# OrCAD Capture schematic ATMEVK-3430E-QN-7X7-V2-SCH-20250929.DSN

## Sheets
1 10. VDDIO-VCCIO Tracking: size B; title: ATM3430E EVALUATION BOARD; rev: 2; note: 084-23-511-xxxx
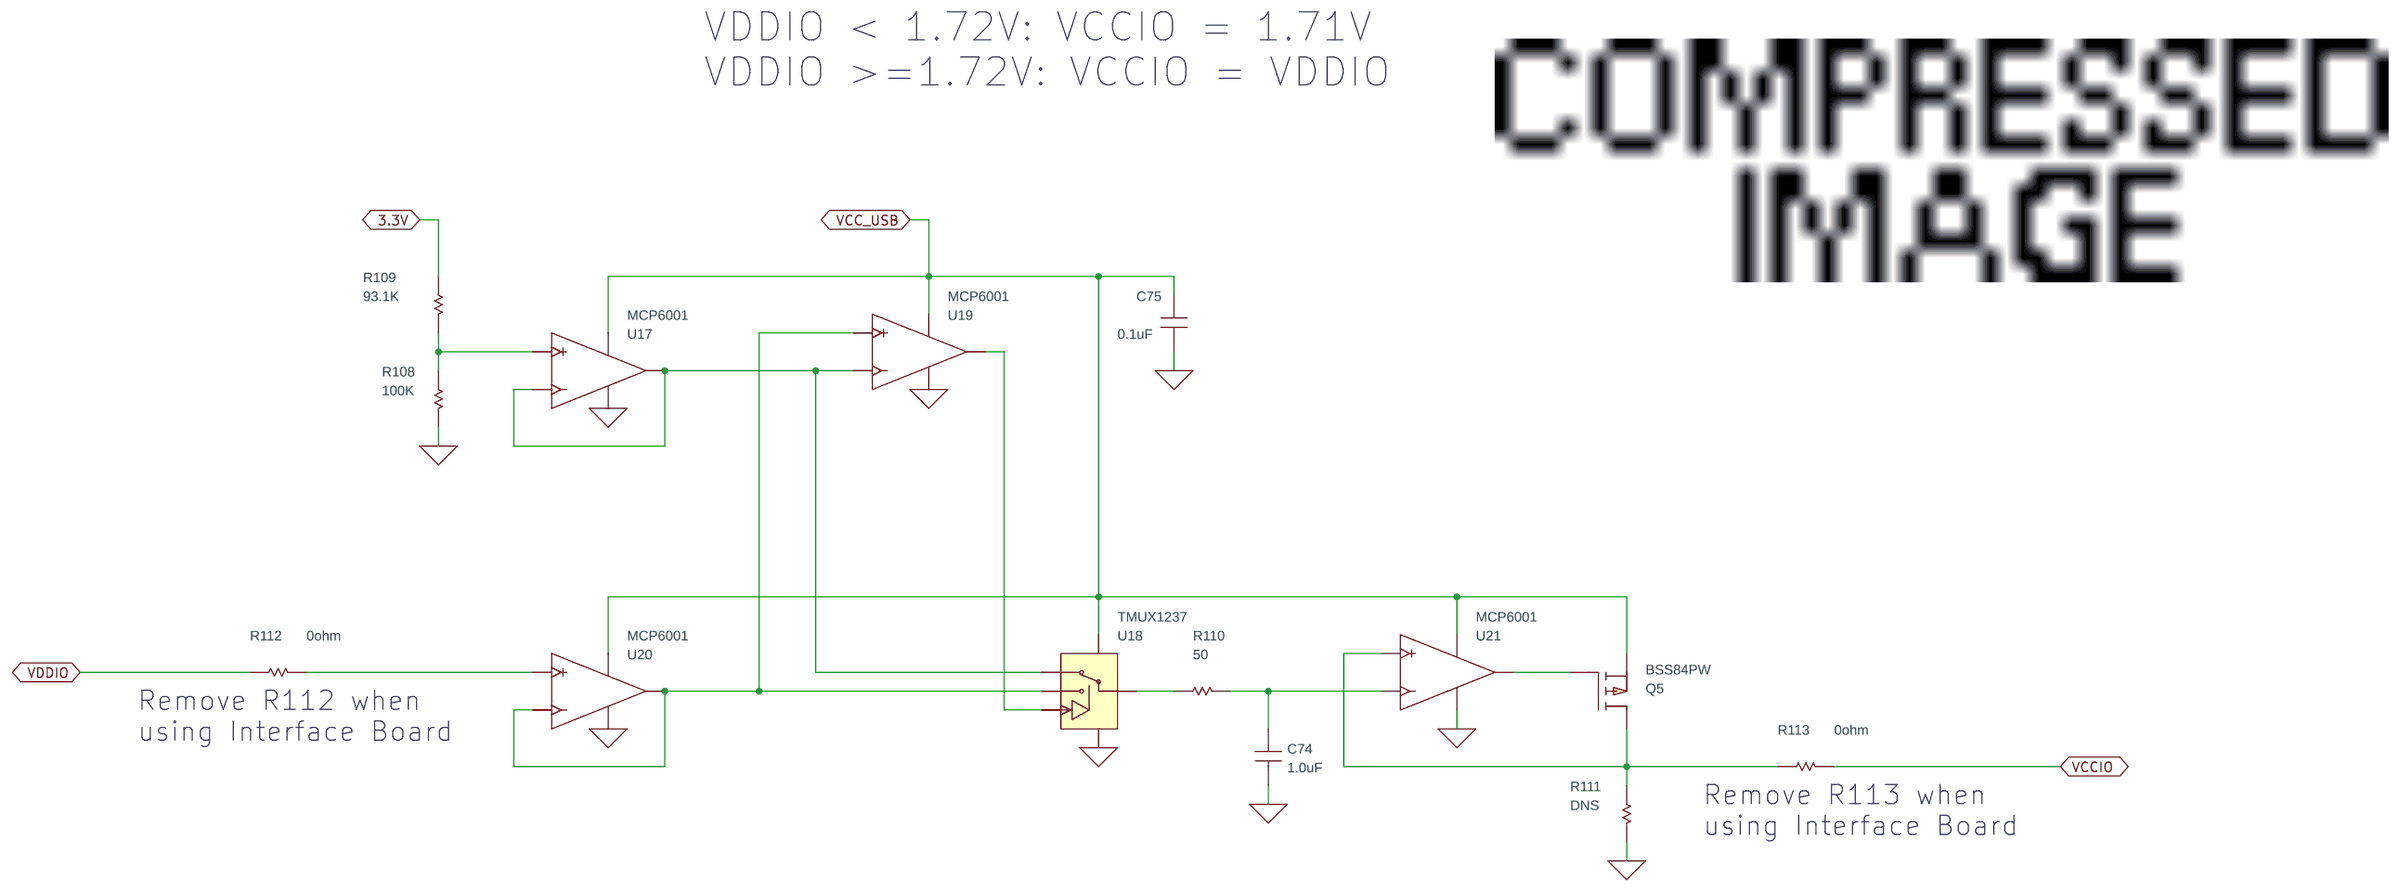
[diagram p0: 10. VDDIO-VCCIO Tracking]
2 11. Power Configuration
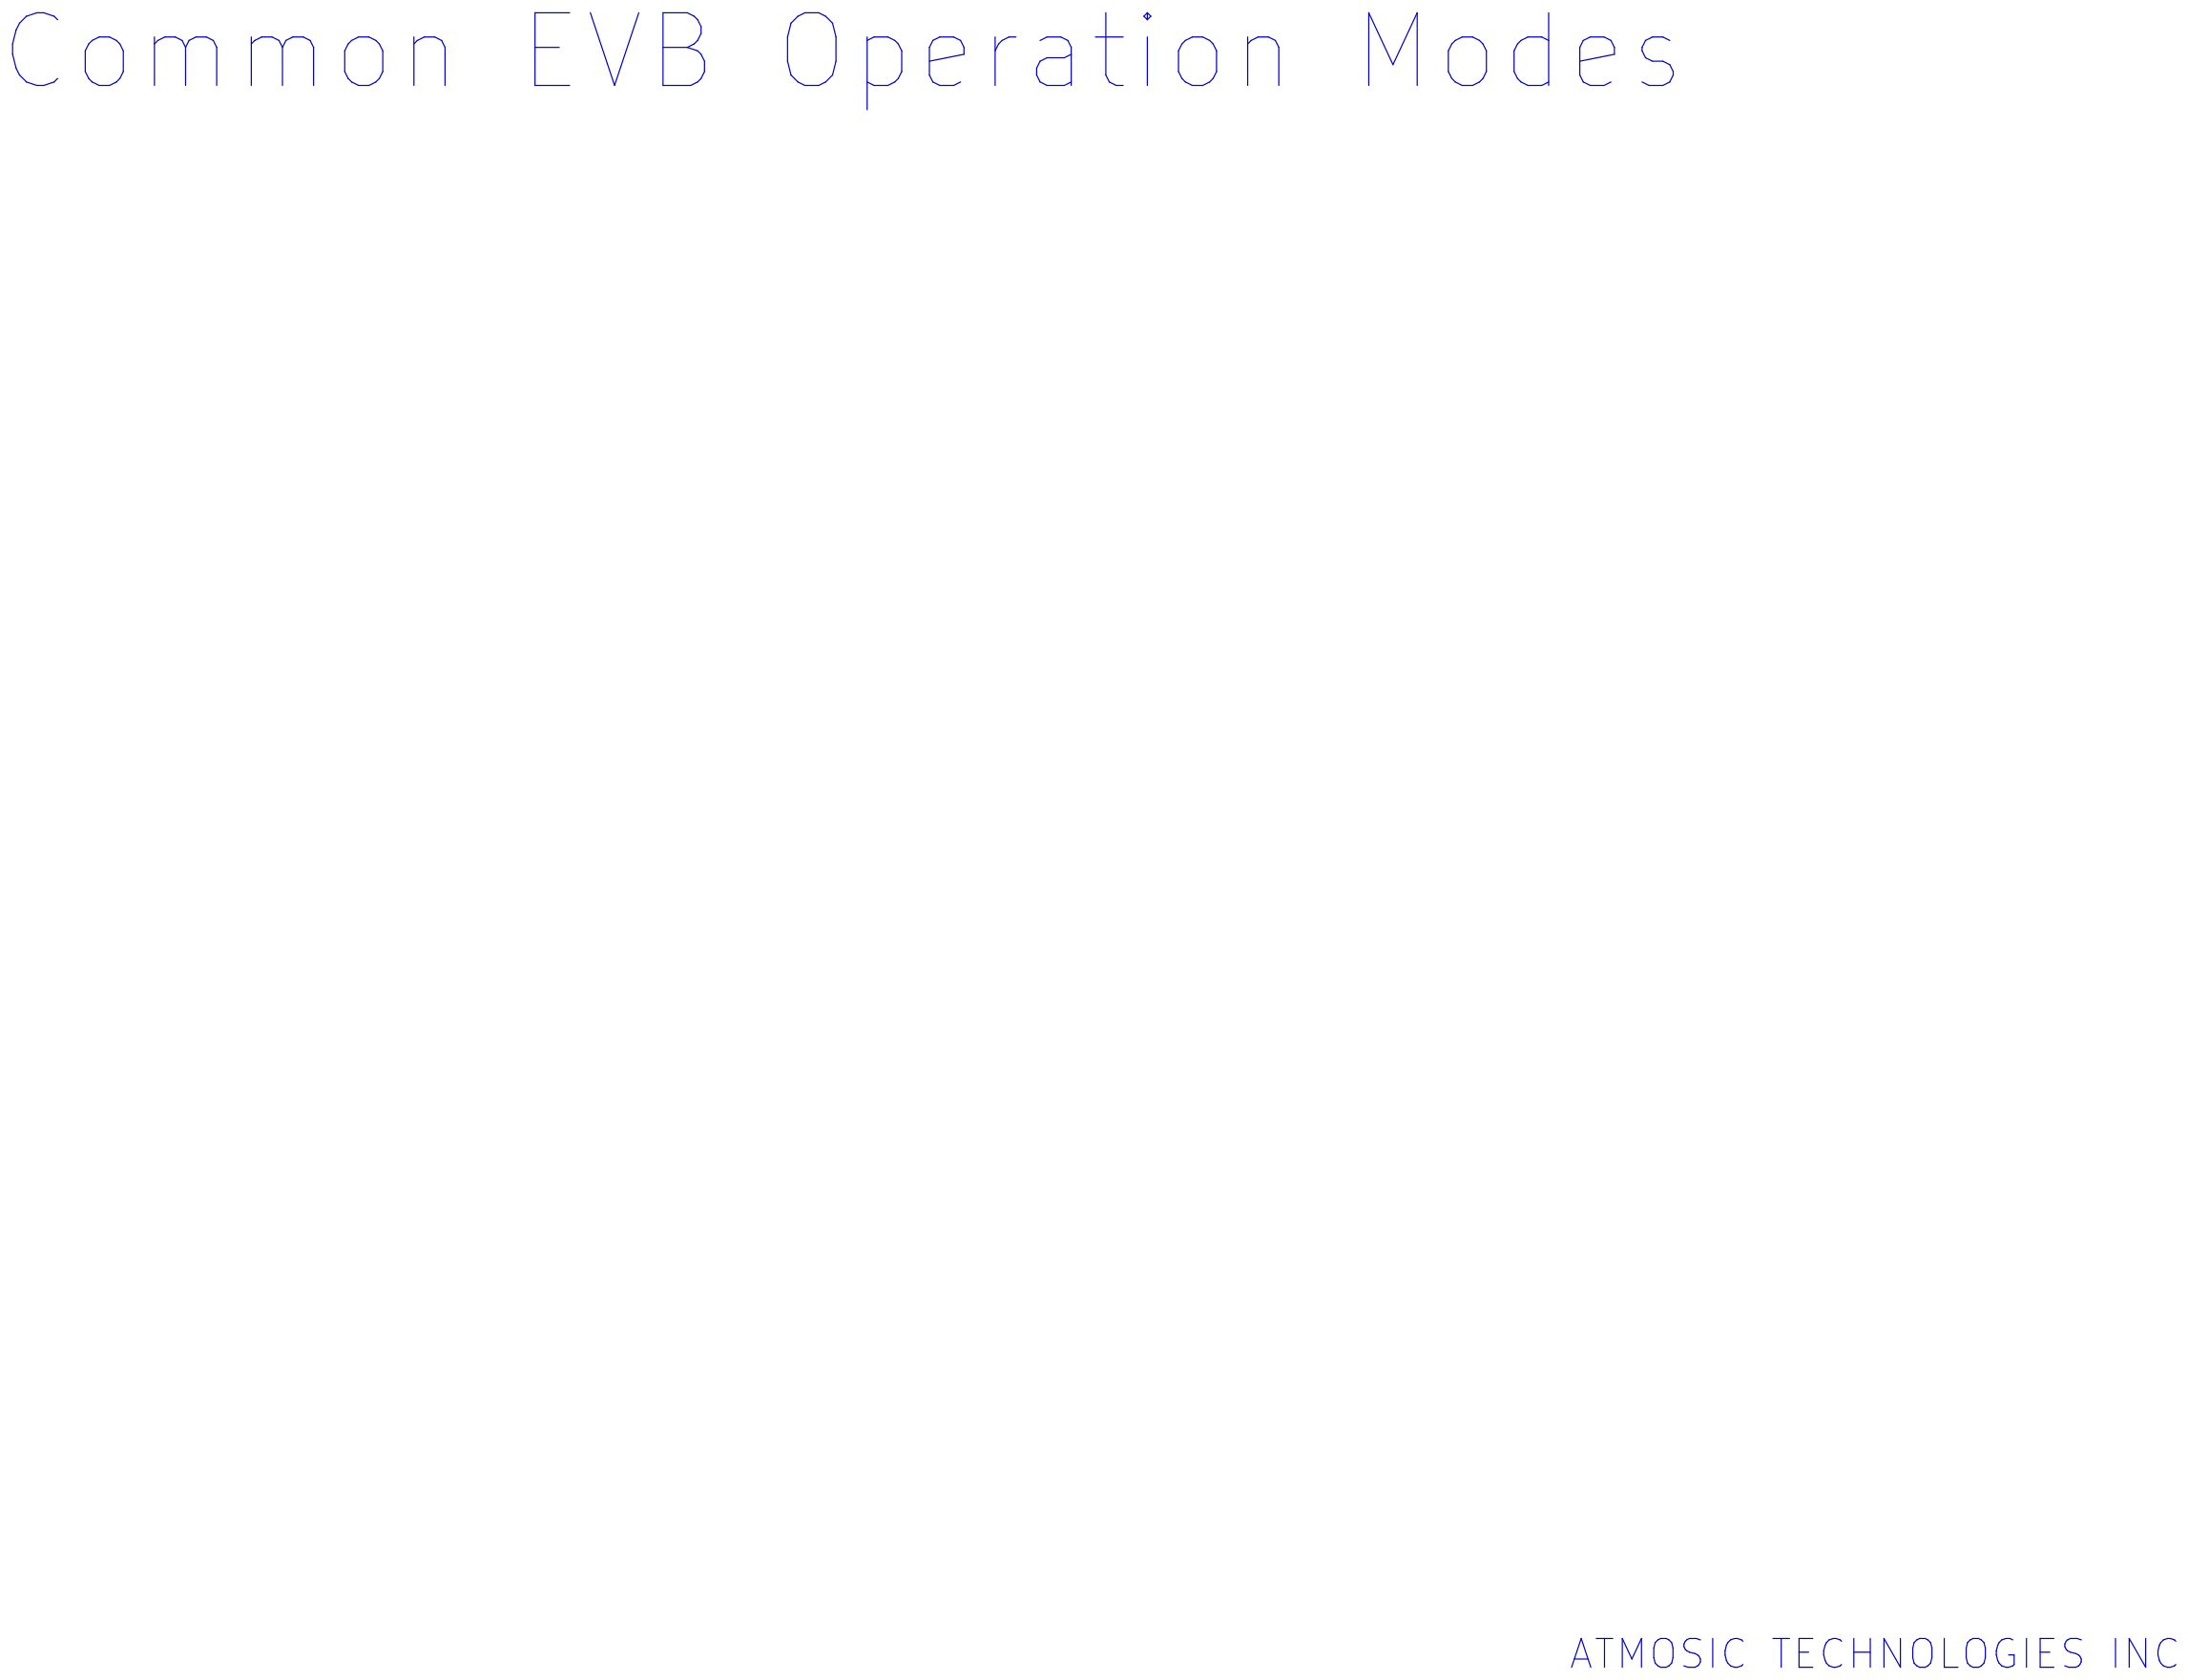
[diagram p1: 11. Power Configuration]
3 01. TITLE
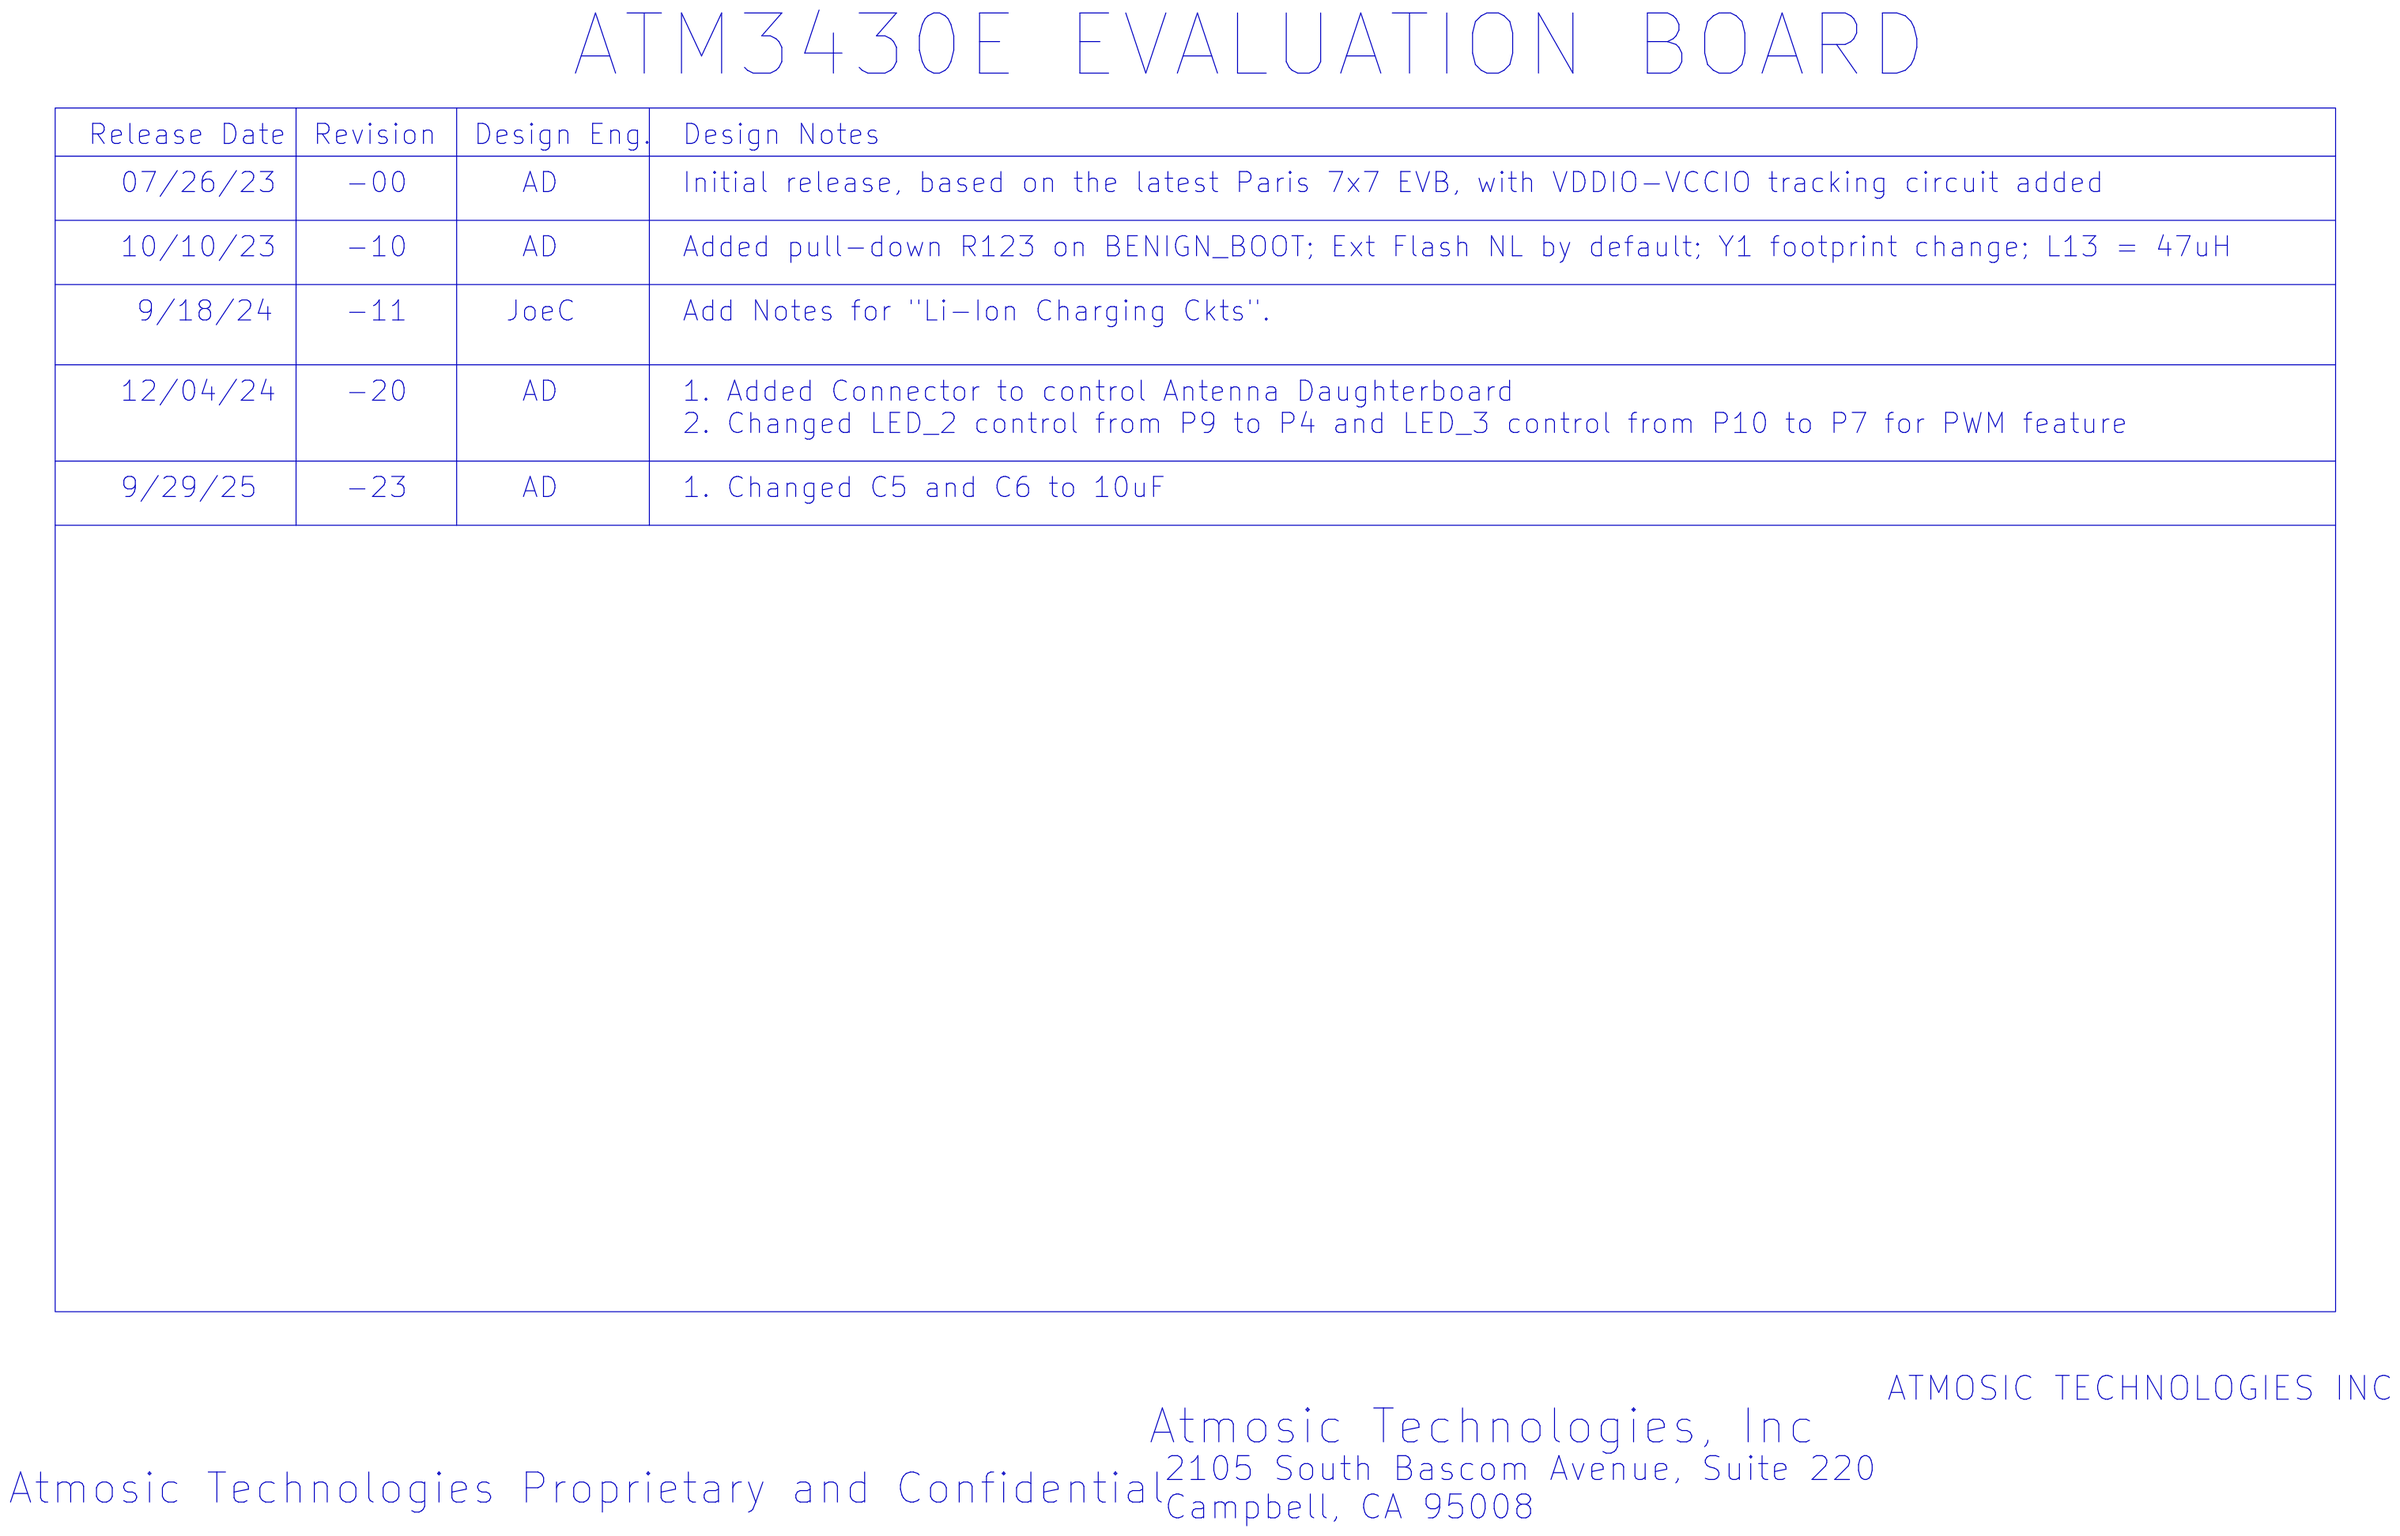
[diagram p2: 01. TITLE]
4 02. Block Diagram
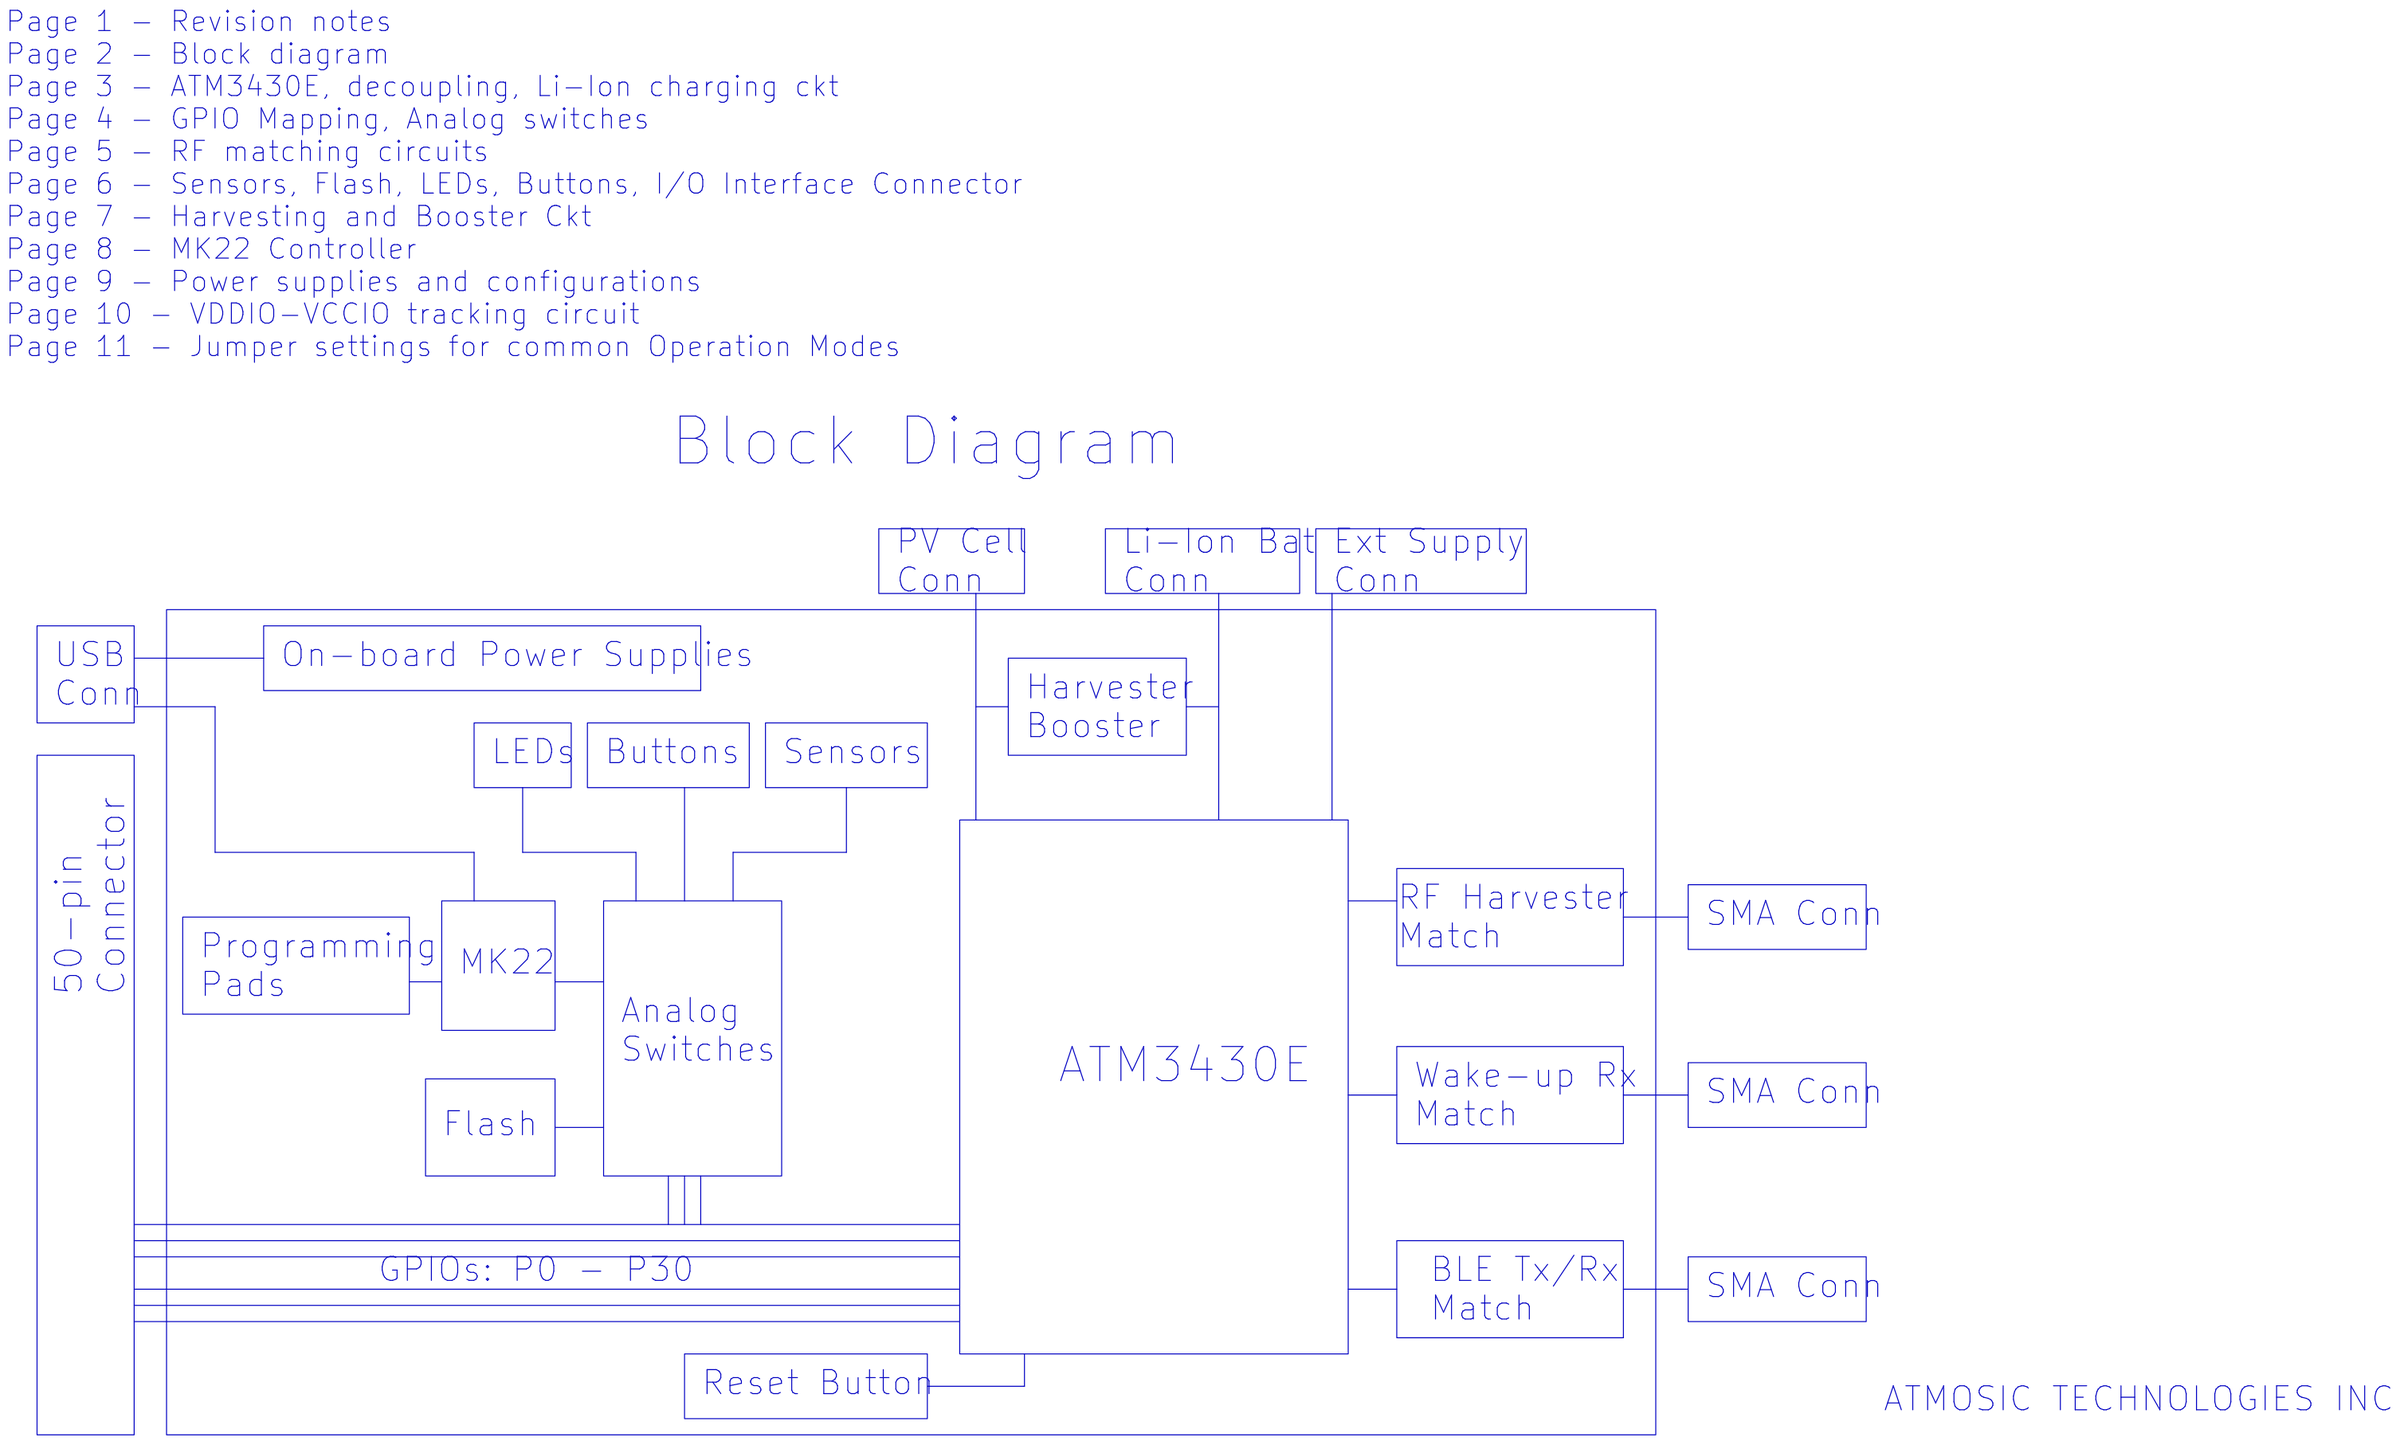
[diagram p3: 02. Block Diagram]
5 03. ATM3430E: size B
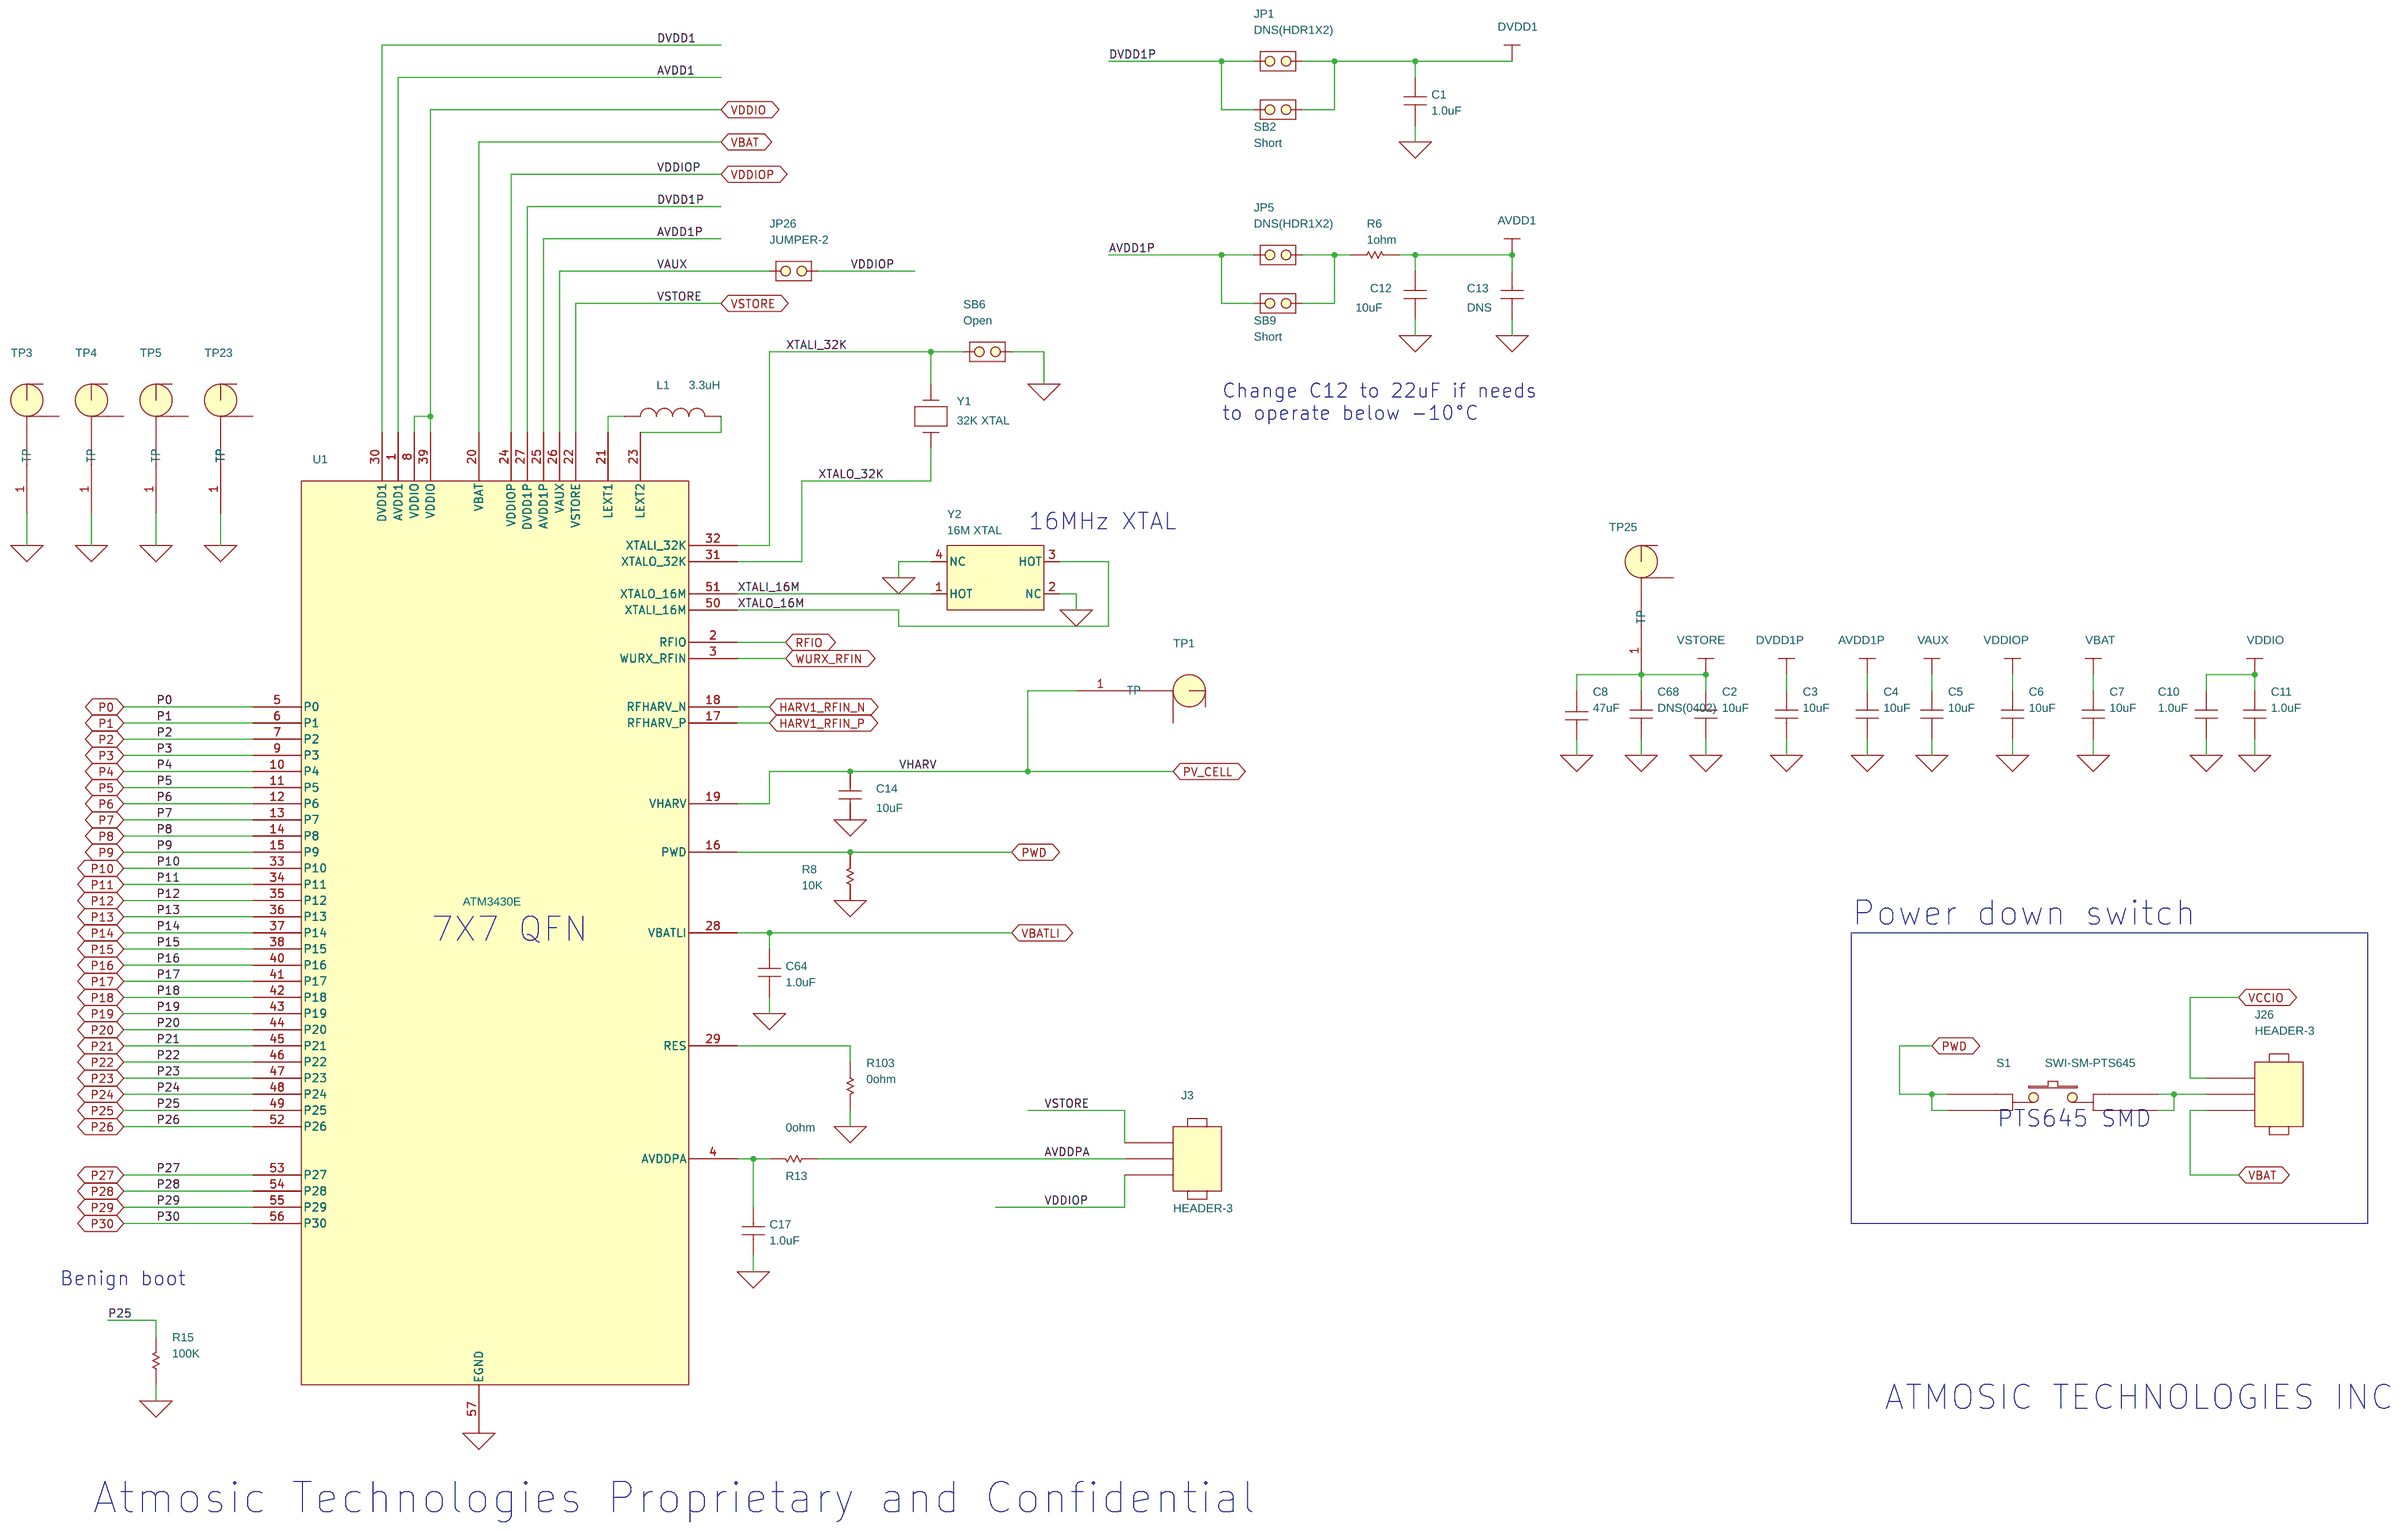
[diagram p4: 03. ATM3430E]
6 04. GPIO Mapping: size B
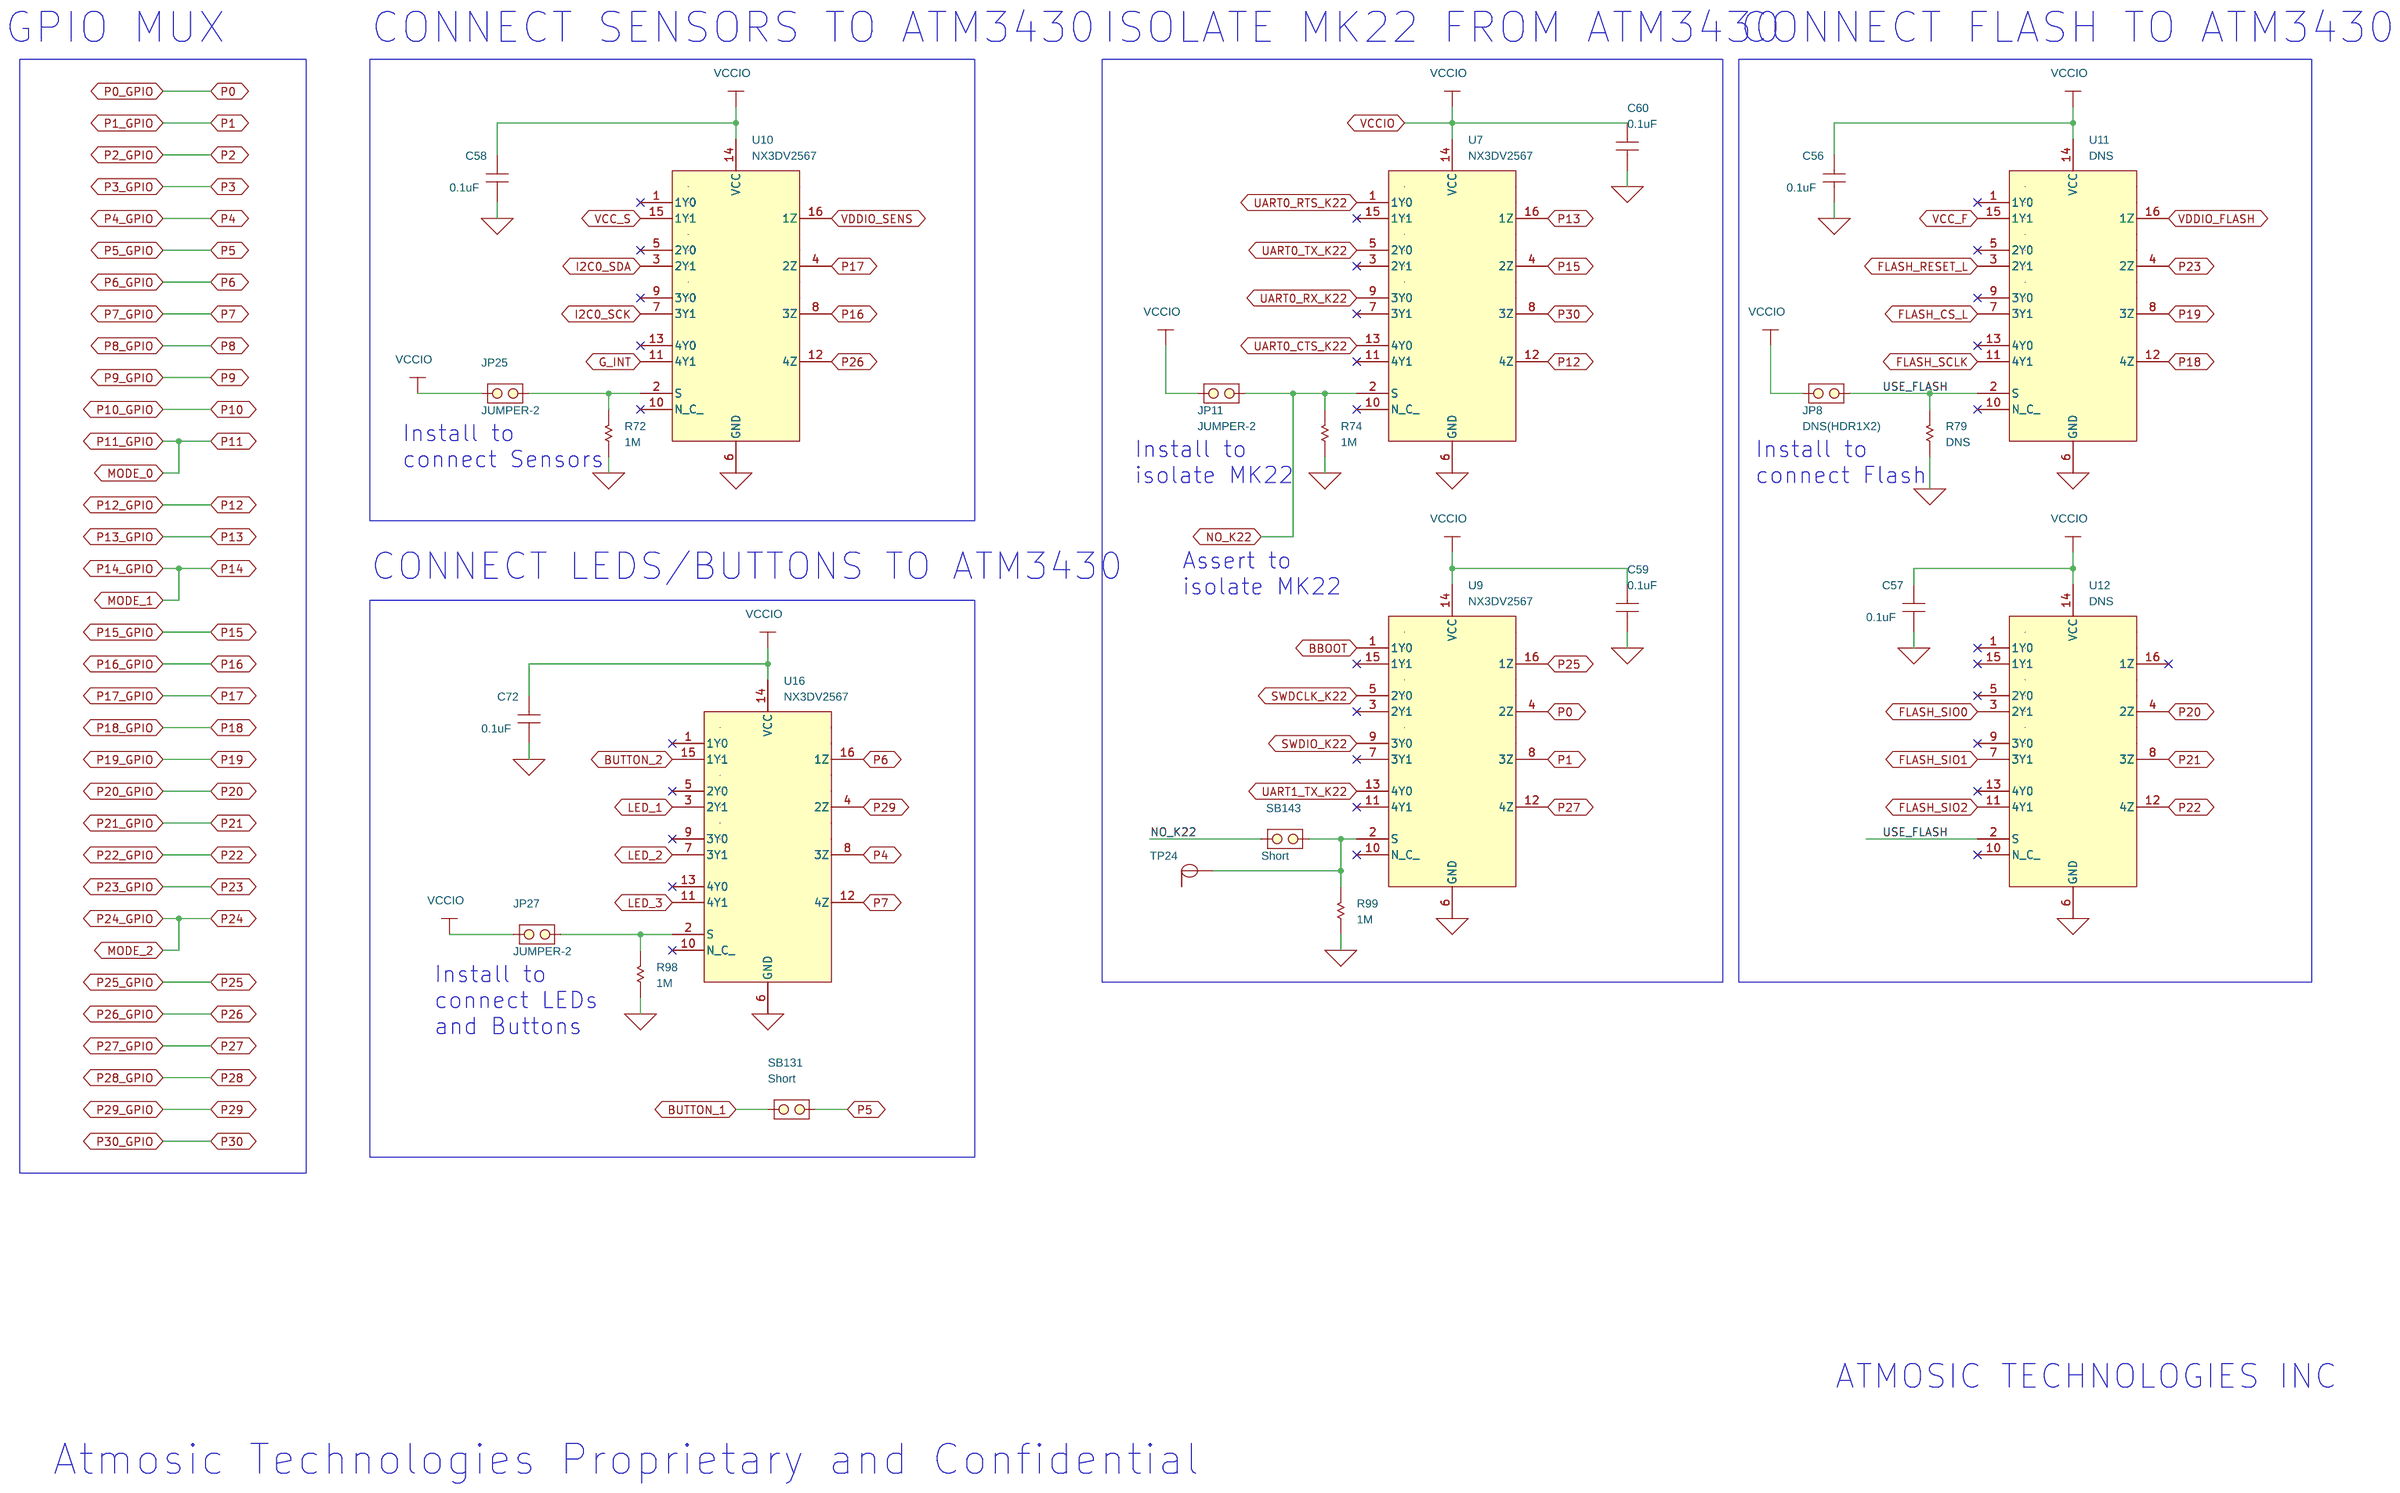
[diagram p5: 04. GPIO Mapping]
7 07. Harvesting: size B
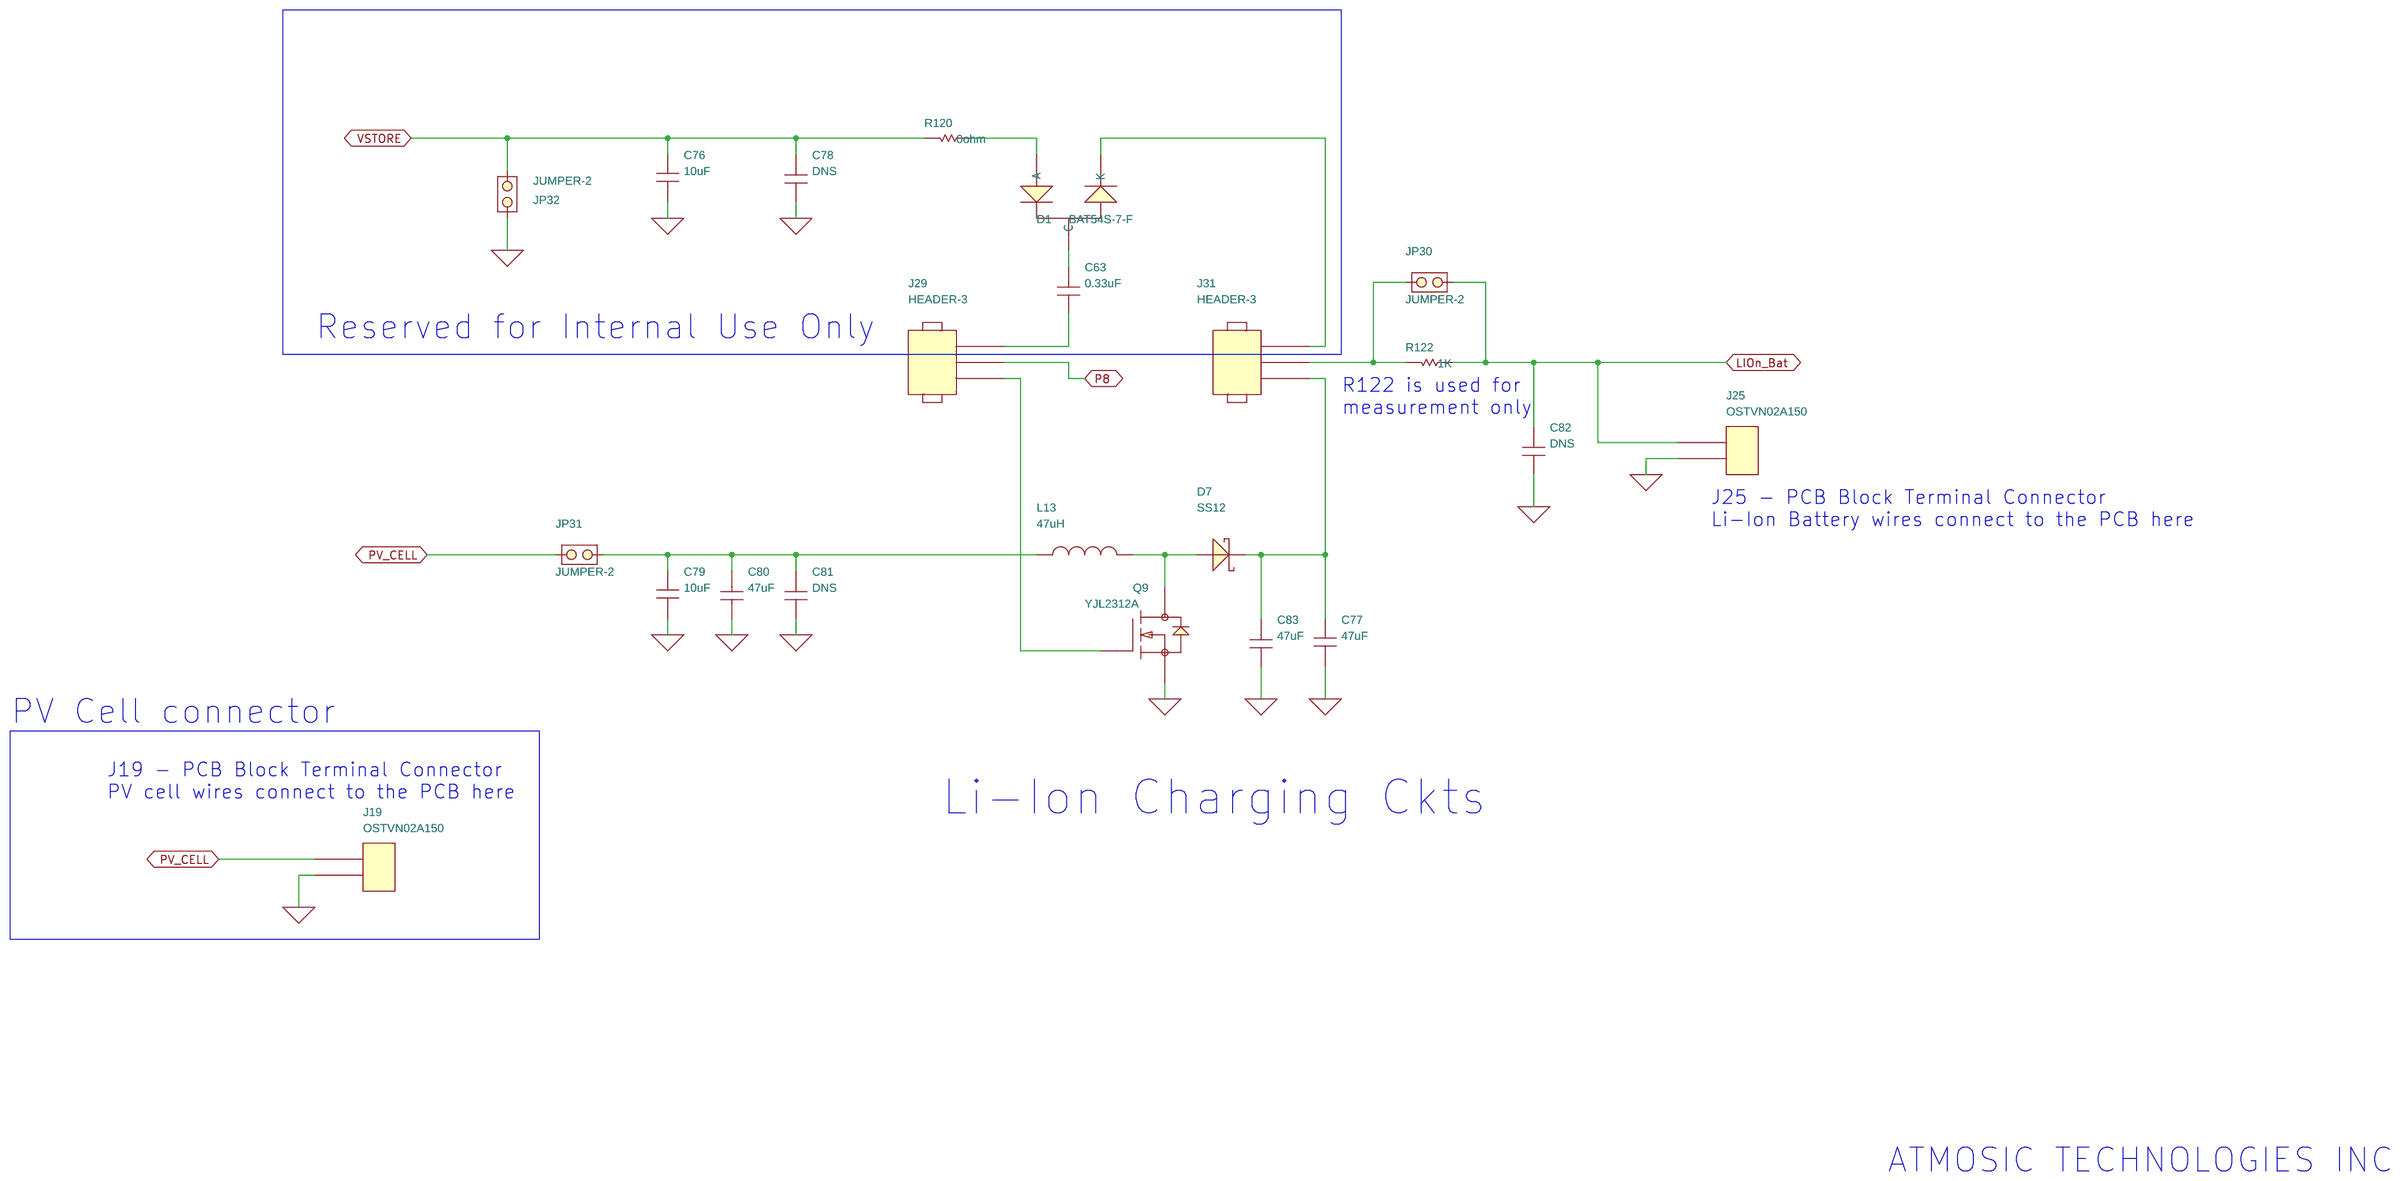
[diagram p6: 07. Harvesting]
8 08. MK22: size B
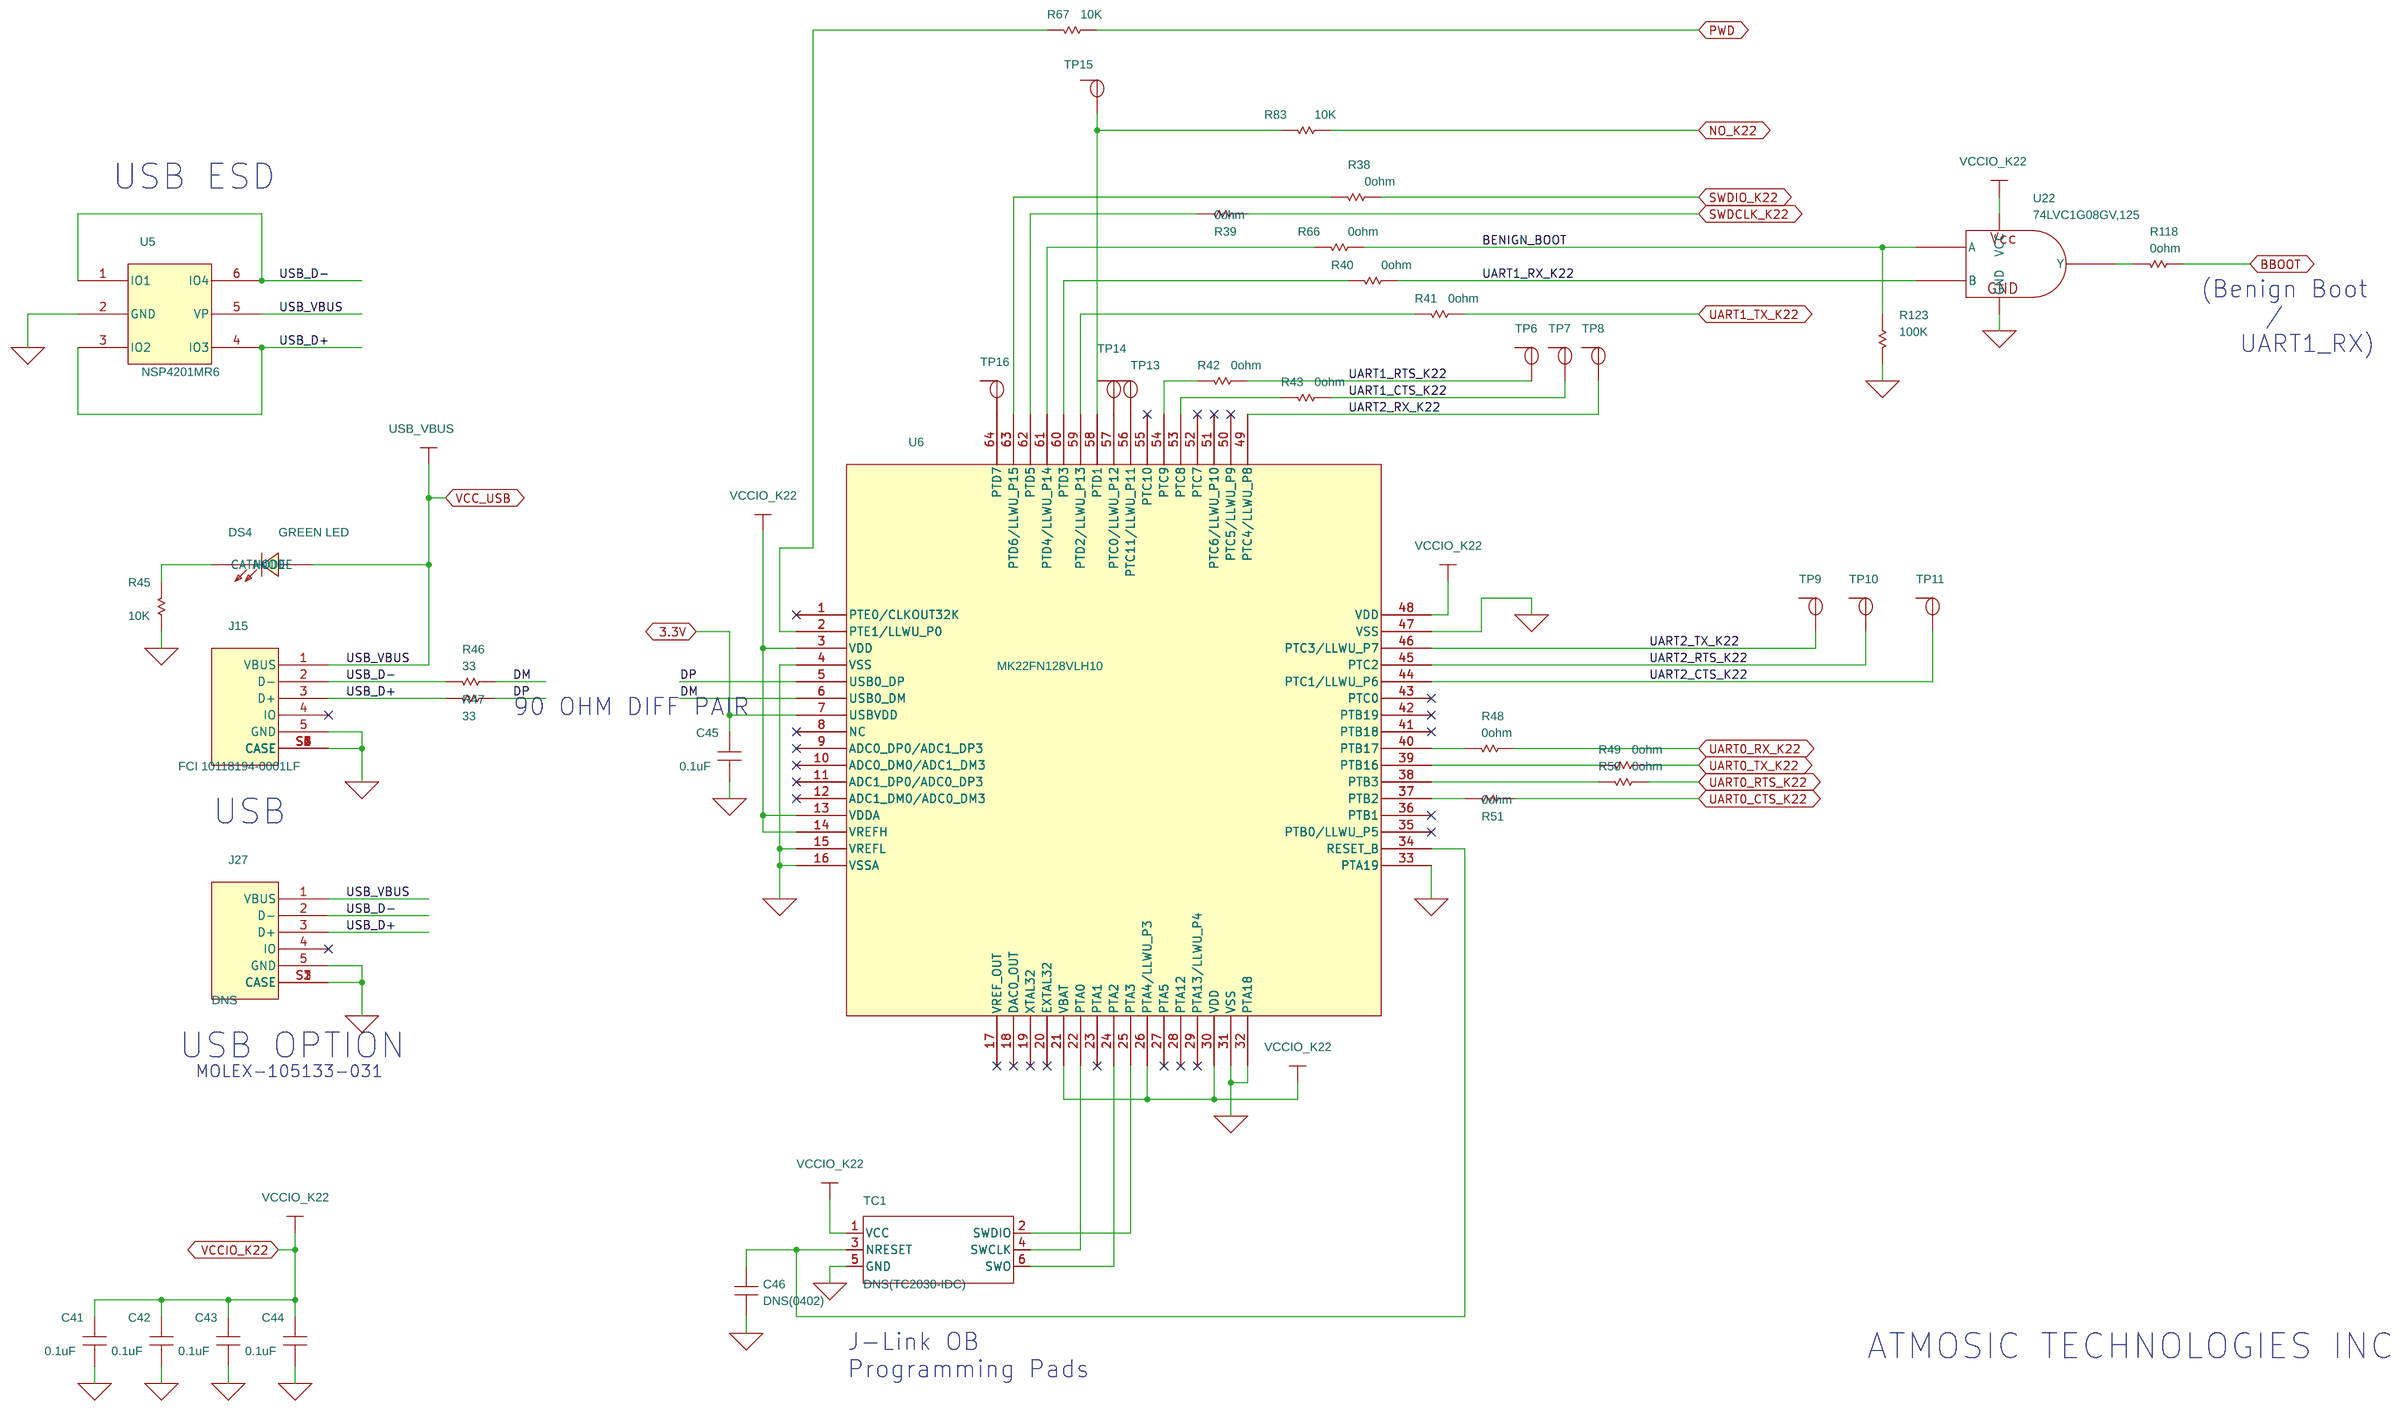
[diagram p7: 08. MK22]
9 09. Power: size B
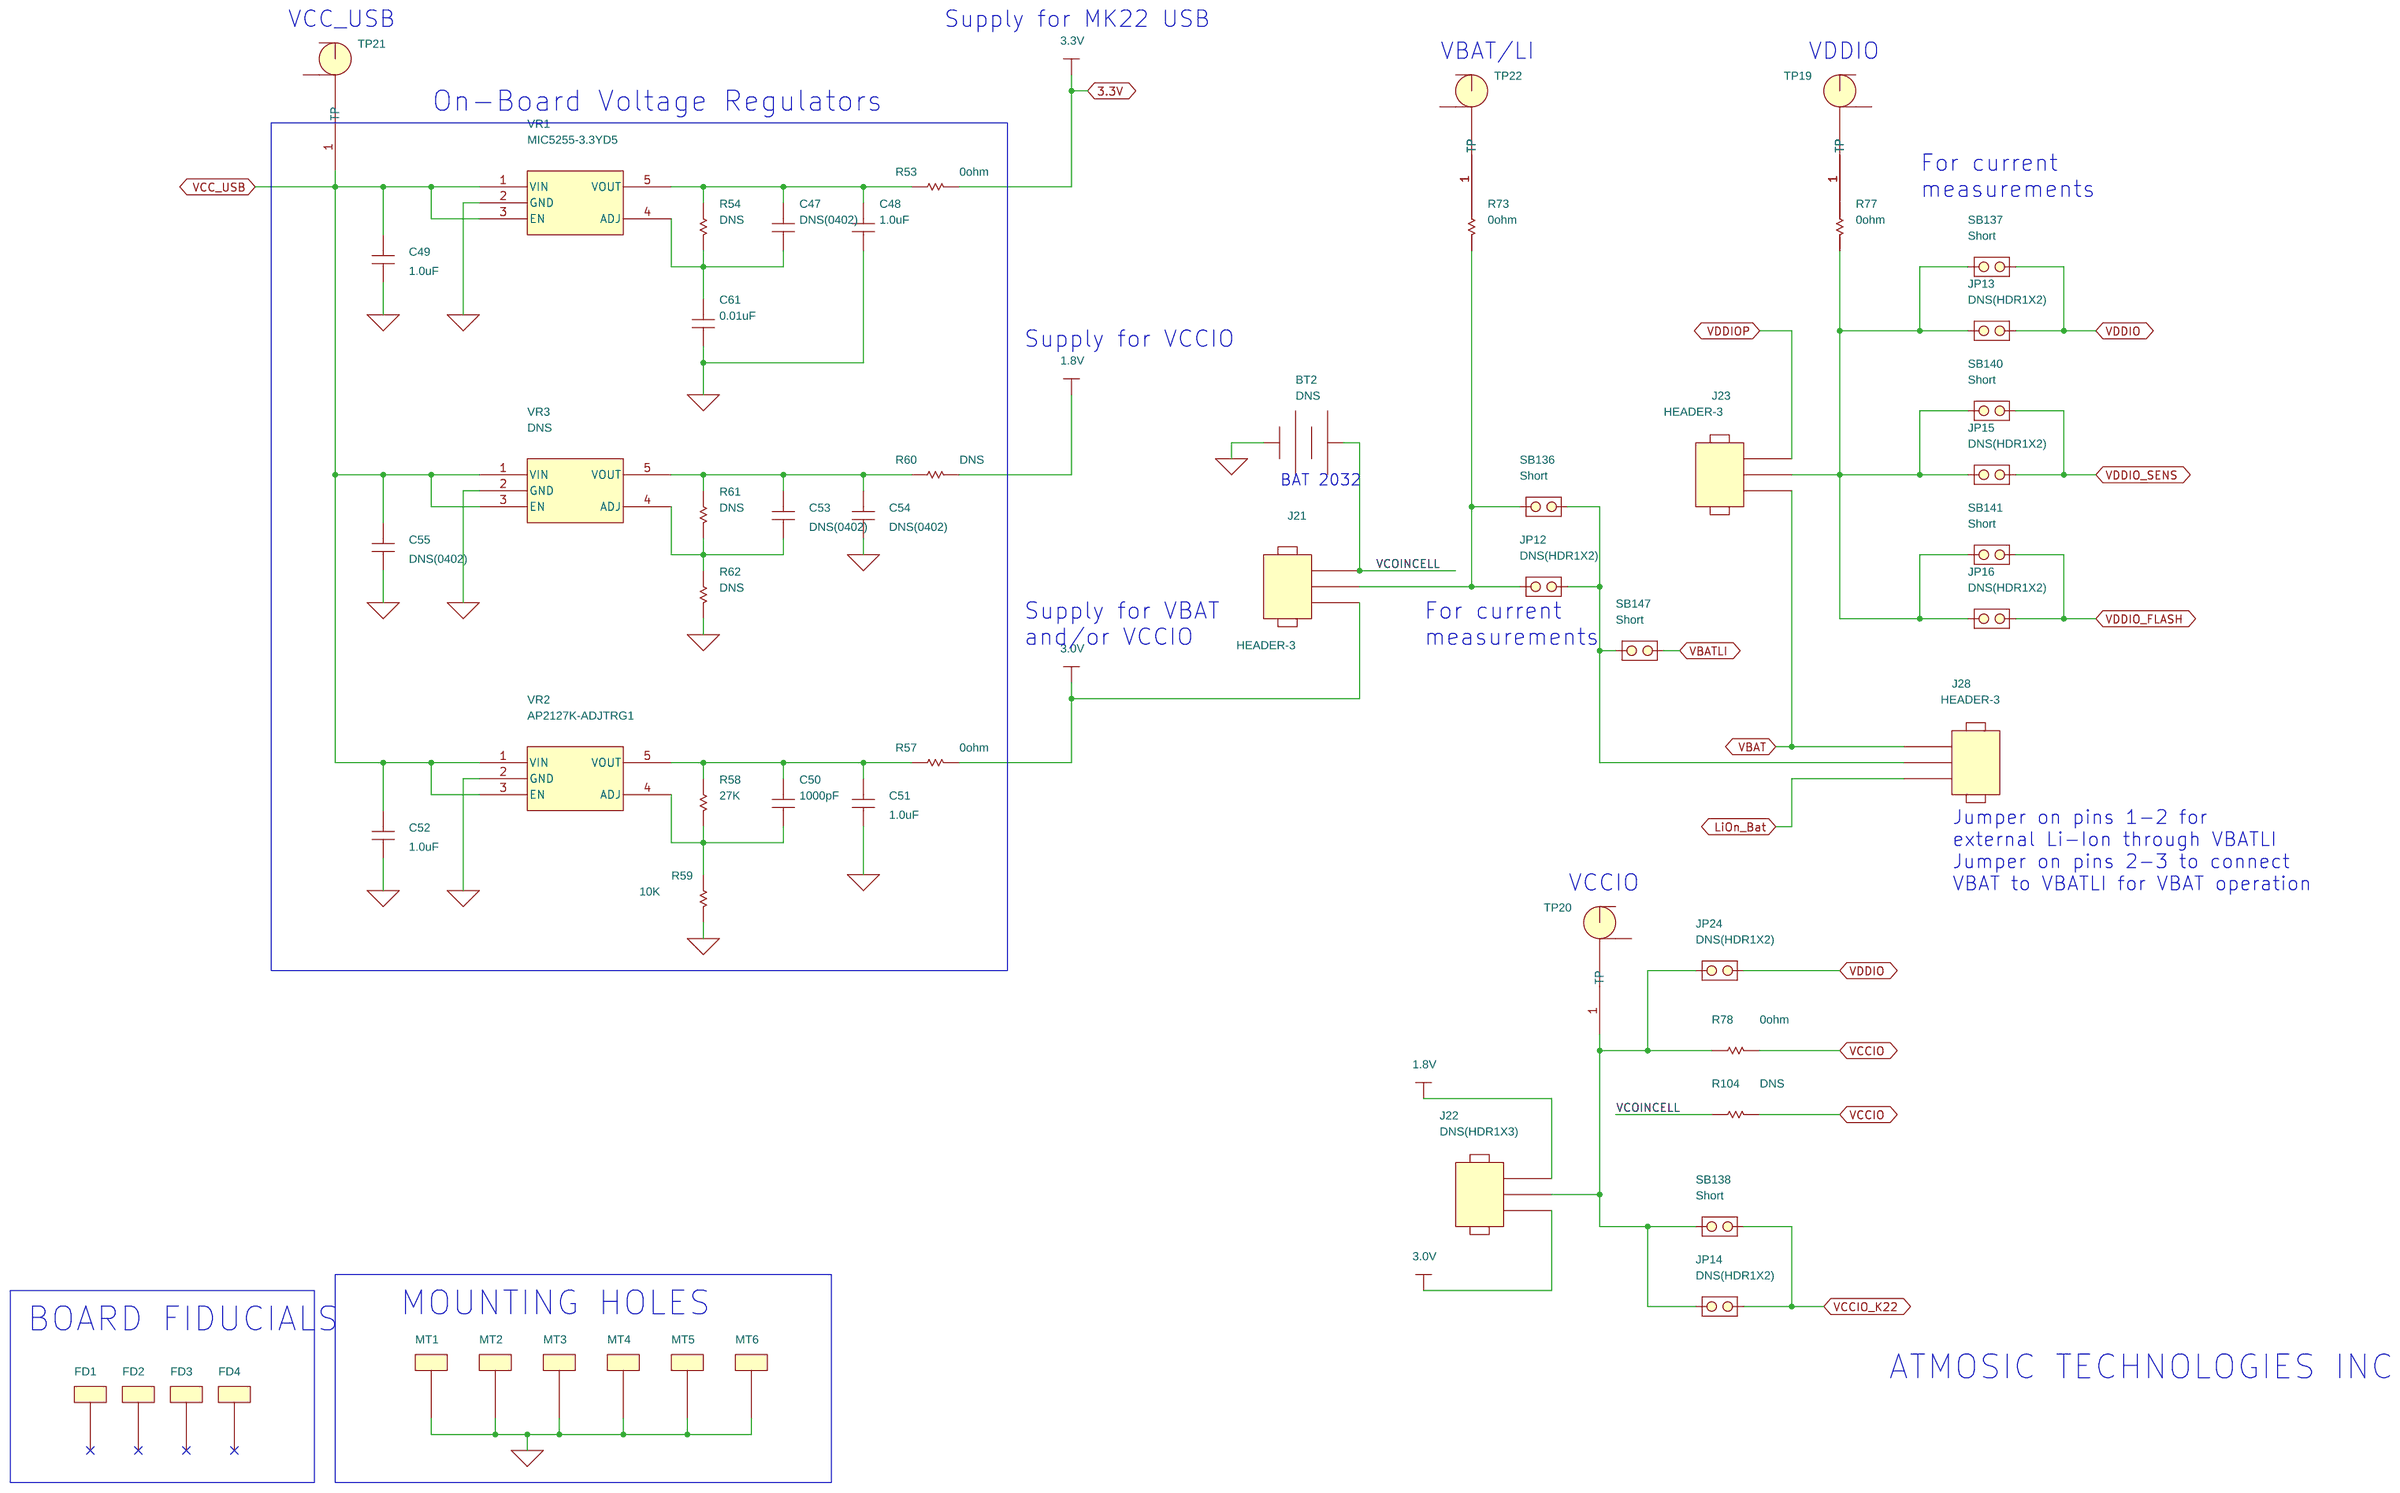
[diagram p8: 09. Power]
10 05. RF (RFIO/WuRX/HARV): size B
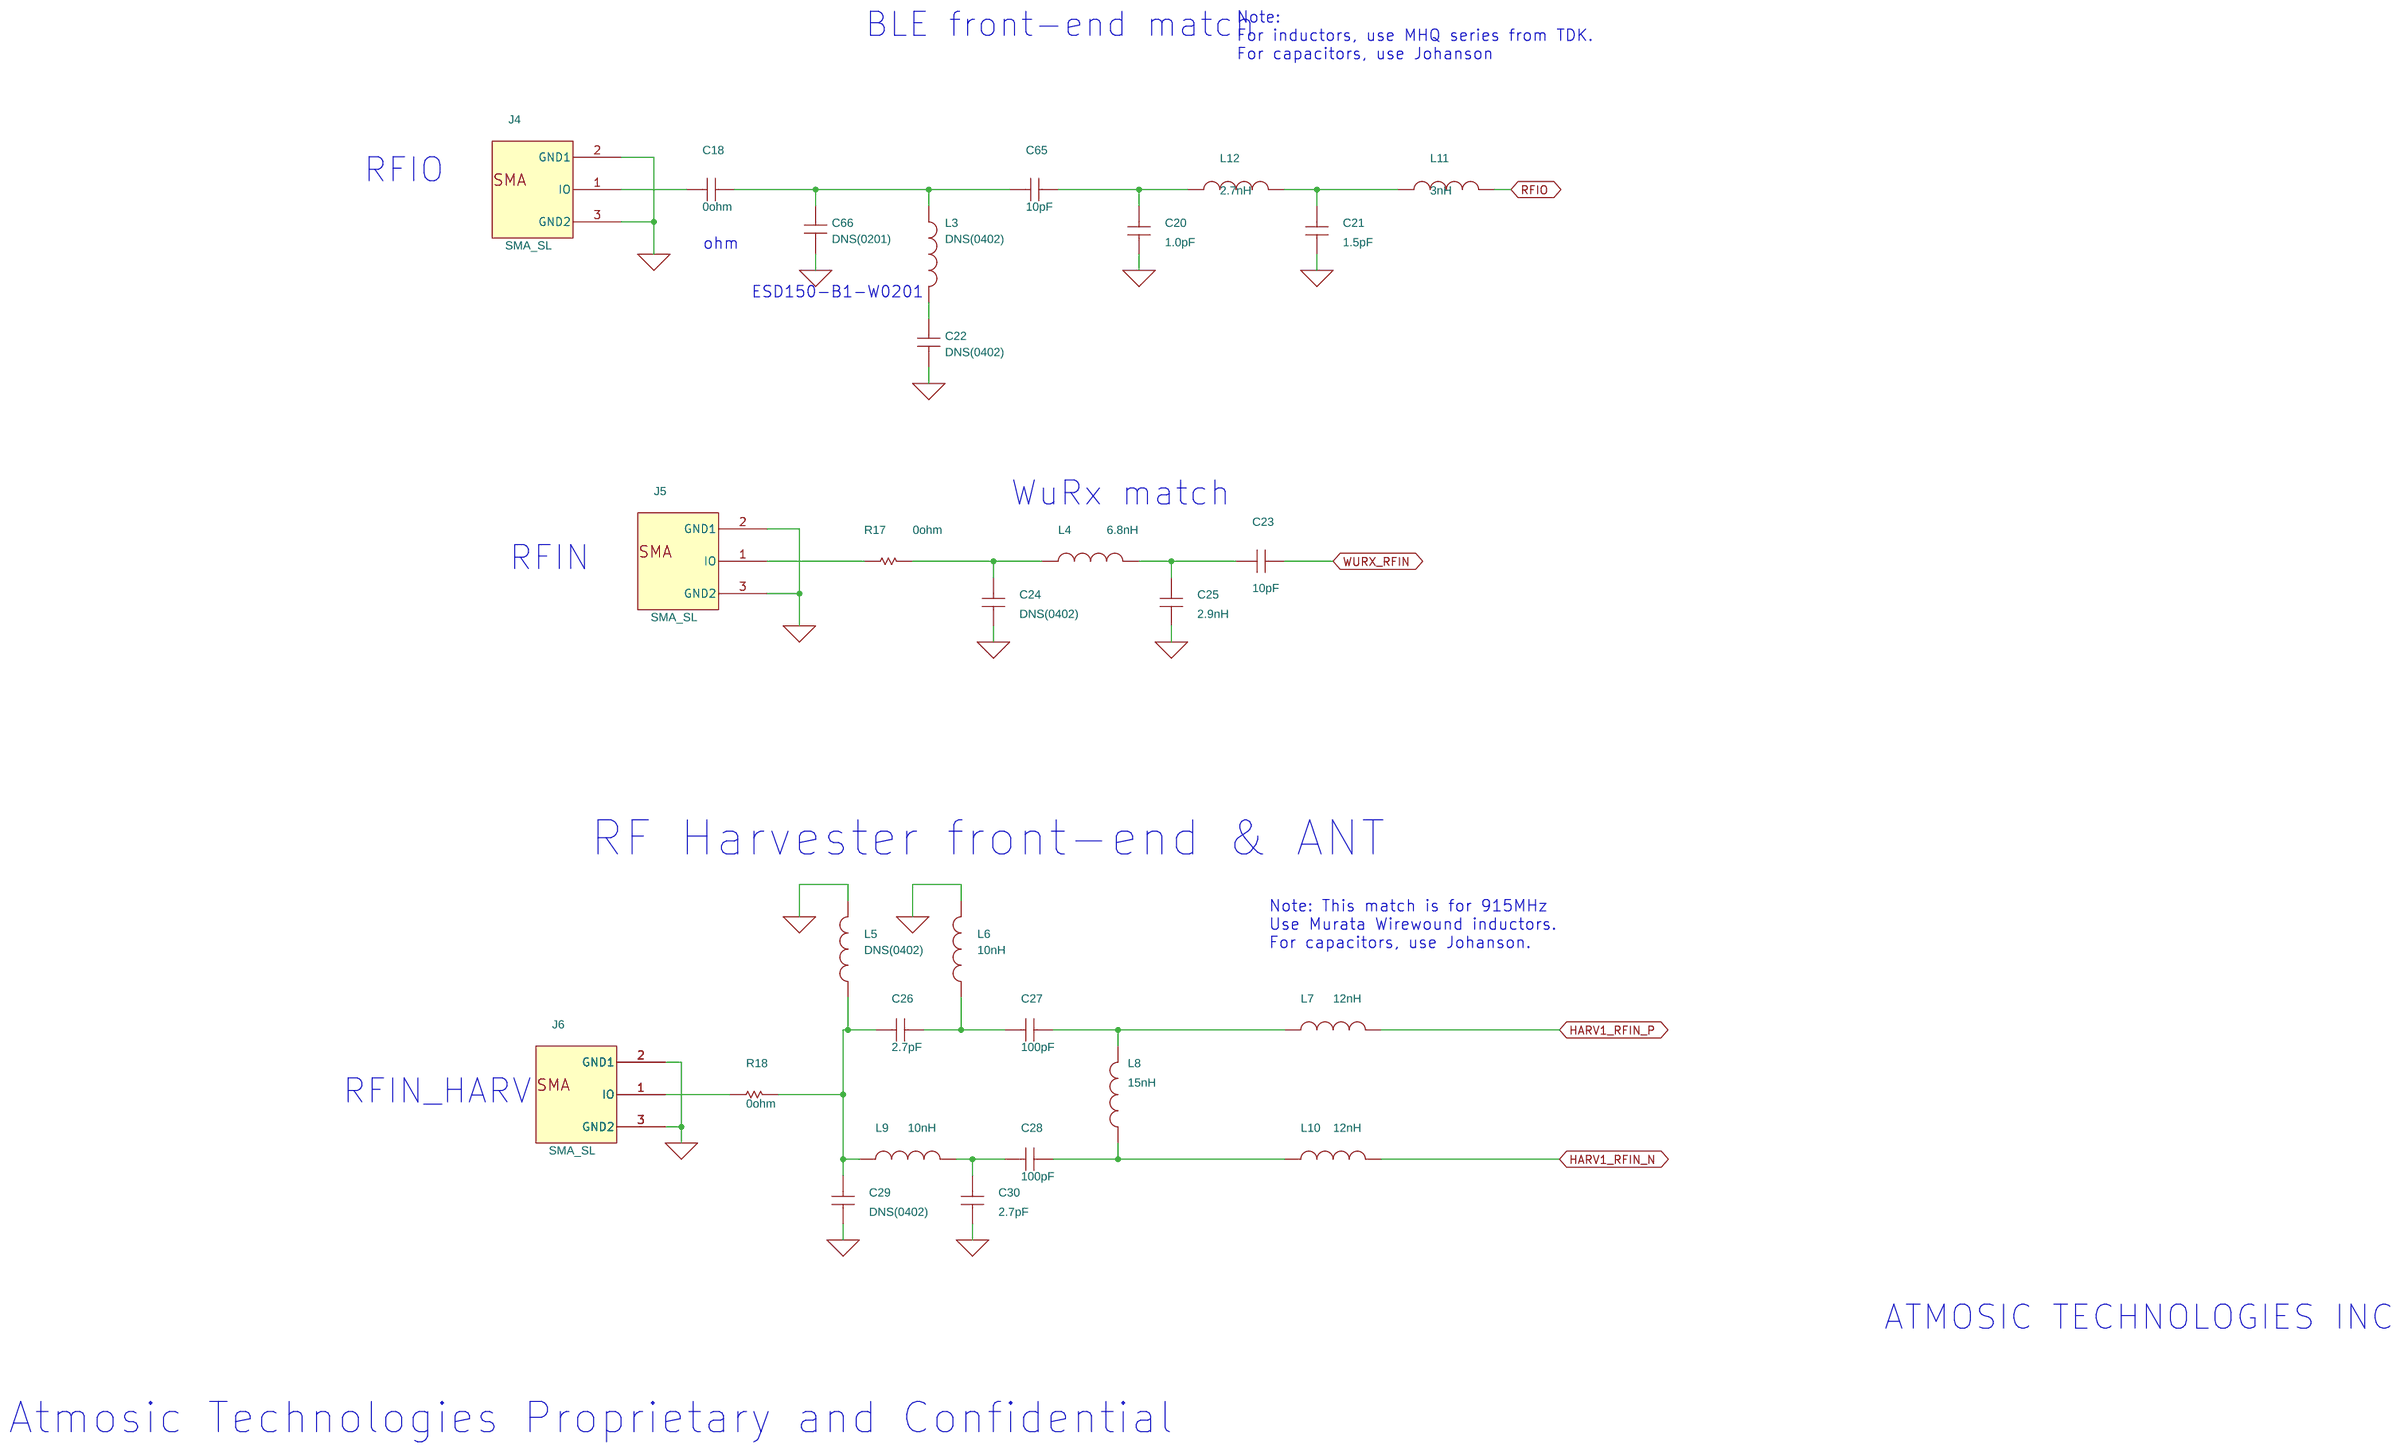
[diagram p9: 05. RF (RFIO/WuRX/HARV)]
11 06. Buttons LEDs Sensors I/O: size B
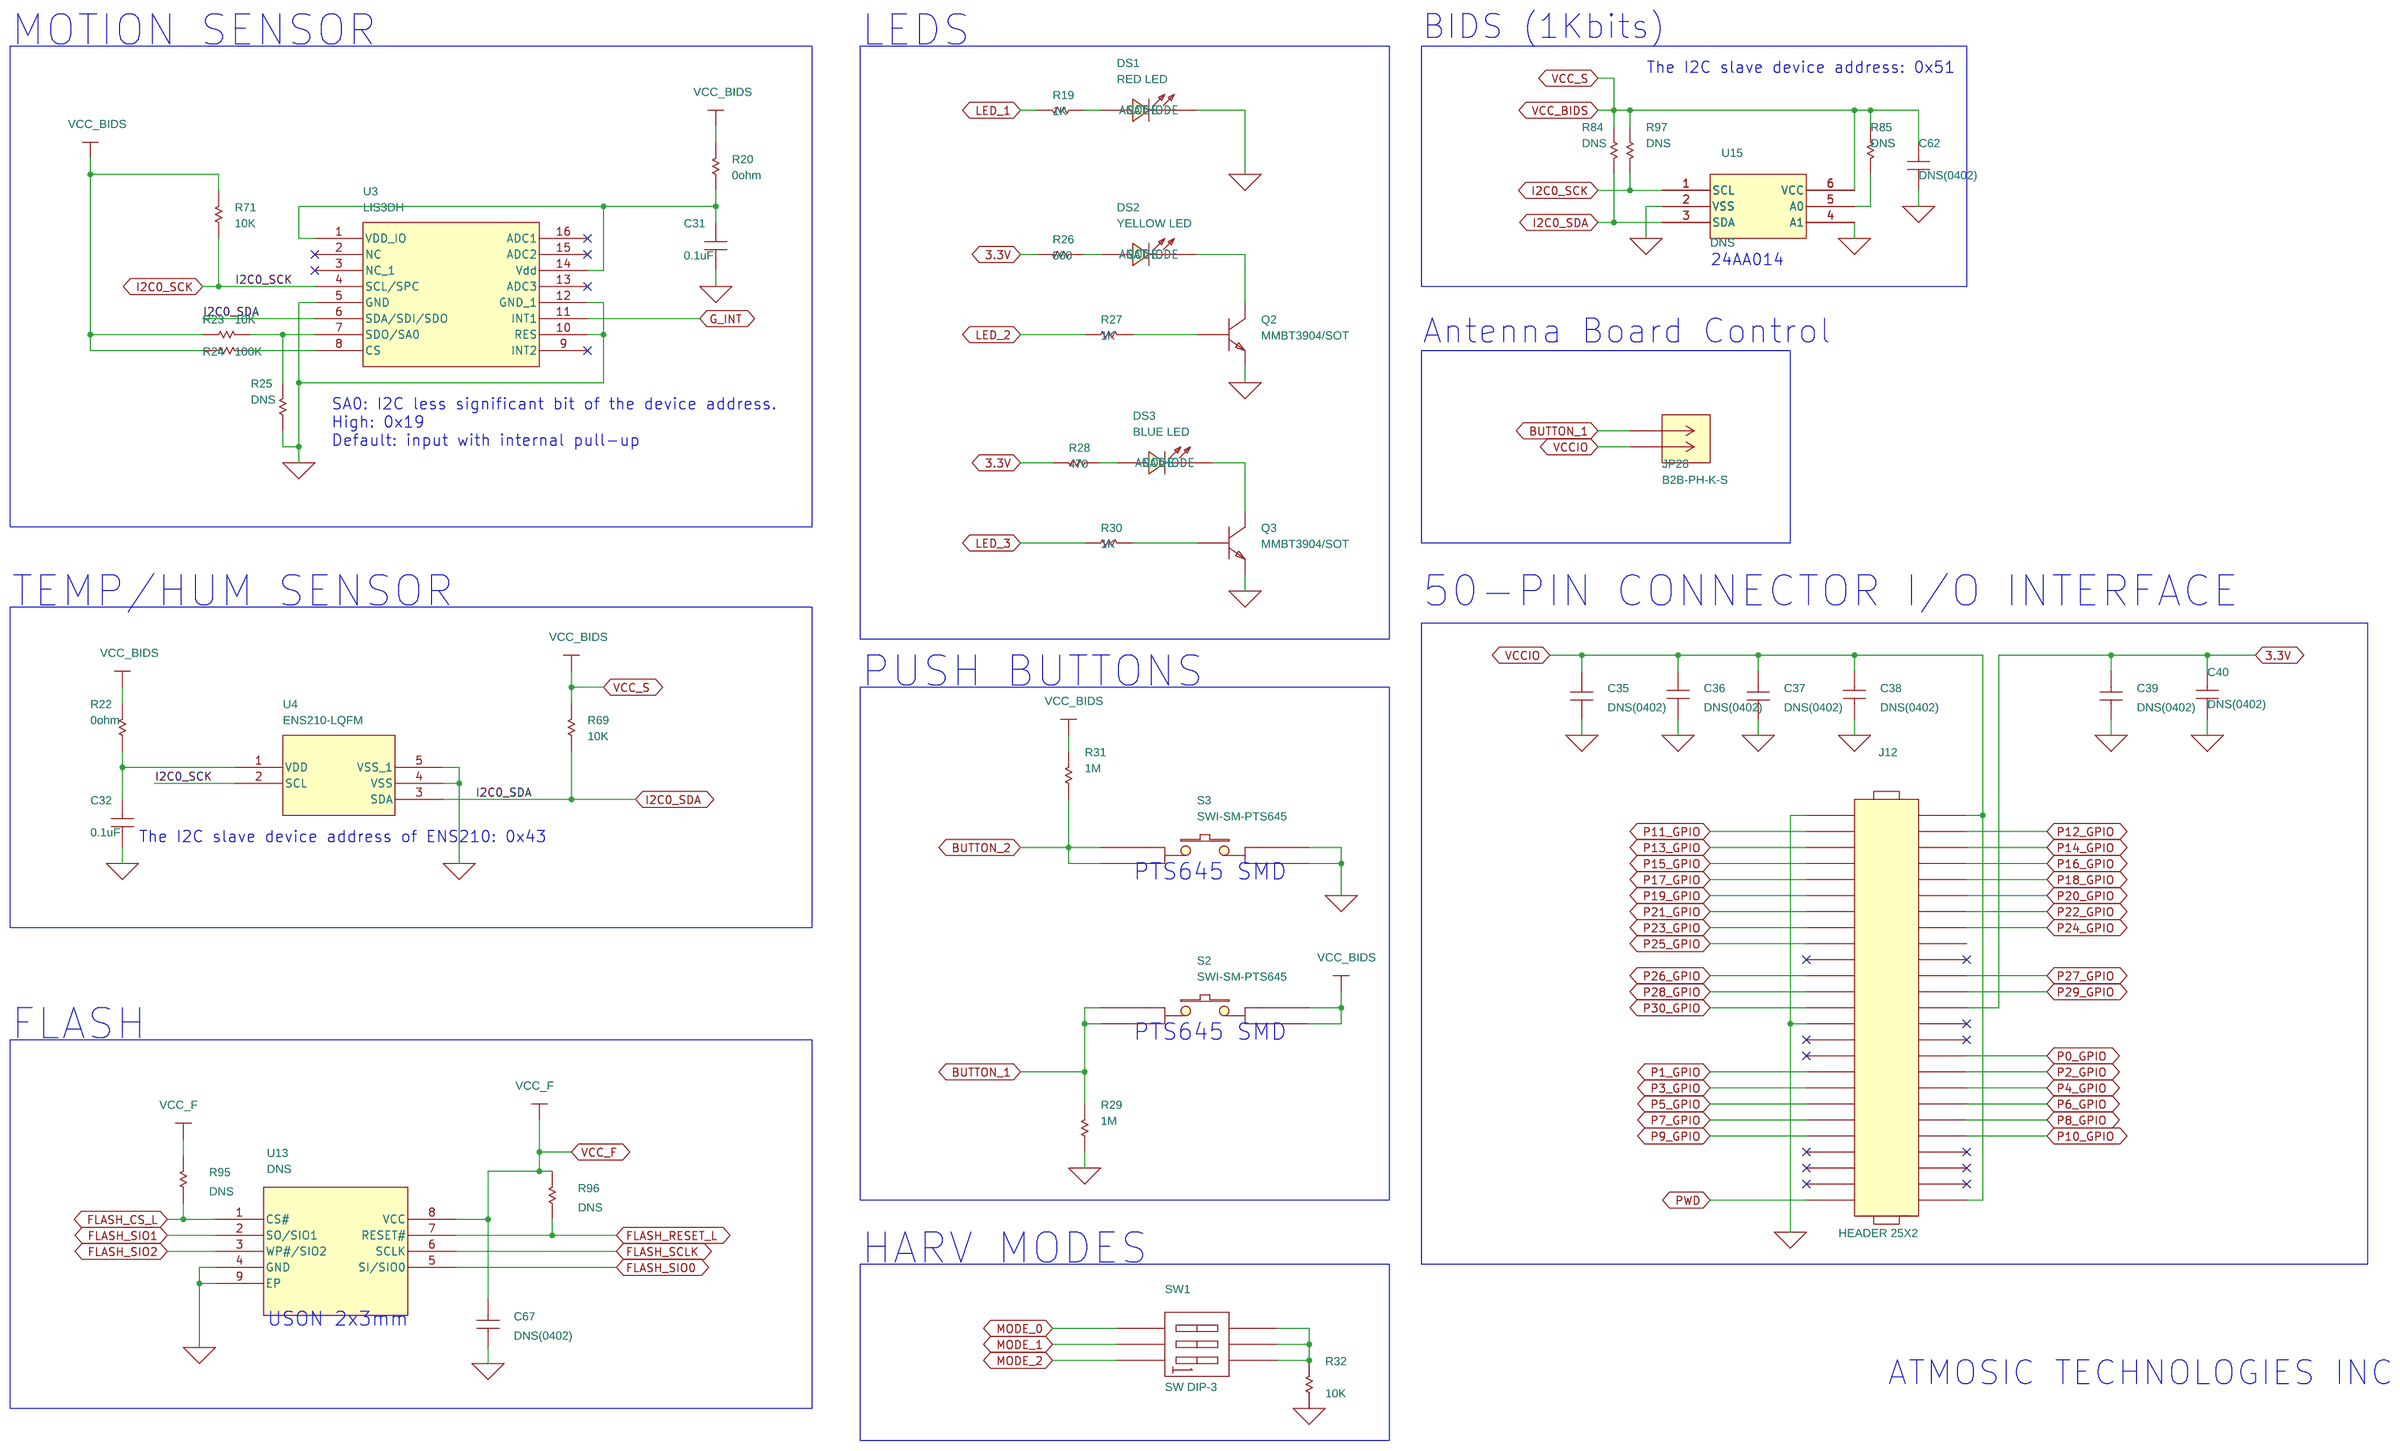
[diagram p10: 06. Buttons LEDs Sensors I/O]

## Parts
sheet 03. ATM3430E
C1  1.0uF  [0402]
C2  10uF  [0402]
C3  10uF  [0402]
C4  10uF  [0402]
C5  10uF  [0402]
C6  10uF  [0402]
C7  10uF  [0402]
C8  47uF  [1206]
C10  1.0uF  [0402]
C11  1.0uF  [0402]
C12  10uF  [0603]
C13  DNS  [0603]
C14  10uF  [0402]
C17  1.0uF  [0402]
C64  1.0uF  [0402]
C68  DNS(0402)  [0402]
J3  HEADER-3  [HDR1X3]
J26  HEADER-3  [HDR1X3]
JP1  DNS(HDR1X2)  [HDR1X2]
JP5  DNS(HDR1X2)  [HDR1X2]
JP26  JUMPER-2  [HDR1X2]
L1  3.3uH  [L_DFE252012F]
R6  1ohm  [0402]
R8  10K  [0402]
R13  0ohm  [0402]
R15  100K  [0402]
R103  0ohm  [0402]
S1  SWI-SM-PTS645  [SWI-SM-PTS645]
SB2  Short  [SB]
SB6  Open  [SB]
SB9  Short  [SB]
TP1  TP-WHT  [TESTPIN]
TP3  TP-BLK  [TESTPIN]
TP4  TP-BLK  [TESTPIN]
TP5  TP-BLK  [TESTPIN]
TP23  TP-BLK  [TESTPIN]
TP25  TP-WHT  [TESTPIN]
U1  ATM3430E  [QFN-56-7X7-0.4MM-EP5.2MM]
Y1  32K XTAL  [XTAL-SMD2-2.0X1.2MM]
Y2  16M XTAL  [XTAL-ECX-2236]
sheet 04. GPIO Mapping
C56  0.1uF  [0402]
C57  0.1uF  [0402]
C58  0.1uF  [0402]
C59  0.1uF  [0402]
C60  0.1uF  [0402]
C72  0.1uF  [0402]
JP8  DNS(HDR1X2)  [HDR1X2]
JP11  JUMPER-2  [HDR1X2]
JP25  JUMPER-2  [HDR1X2]
JP27  JUMPER-2  [HDR1X2]
R72  1M  [0402]
R74  1M  [0402]
R79  DNS  [0402]
R98  1M  [0402]
R99  1M  [0402]
SB131  Short  [SB]
SB143  Short  [SB]
TP24  TP  [TESTPAD50]
U7  NX3DV2567  [XQFN16]
U9  NX3DV2567  [XQFN16]
U10  NX3DV2567  [XQFN16]
U11  DNS  [XQFN16]
U12  DNS  [XQFN16]
U16  NX3DV2567  [XQFN16]
sheet 05. RF (RFIO/WuRX/HARV)
C18  0ohm  [0402]
C20  1.0pF  [0402]
C21  1.5pF  [0402]
C22  DNS(0402)  [0402]
C23  10pF  [0402]
C24  DNS(0402)  [0402]
C25  2.9nH  [0402]
C26  2.7pF  [0402]
C27  100pF  [0402]
C28  100pF  [0402]
C29  DNS(0402)  [0402]
C30  2.7pF  [0402]
C65  10pF  [0402]
C66  DNS(0201)  [0201]
J4  SMA_SL  [SMA-RA]
J5  SMA_SL  [SMA-RA]
J6  SMA_SL  [SMA-RA]
L3  DNS(0402)  [0402]
L4  6.8nH  [0402]
L5  DNS(0402)  [0402]
L6  10nH  [0402]
L7  12nH  [0402]
L8  15nH  [0402]
L9  10nH  [0402]
L10  12nH  [0402]
L11  3nH  [0402]
L12  2.7nH  [0402]
R17  0ohm  [0402]
R18  0ohm  [0402]
sheet 06. Buttons LEDs Sensors I/O
C31  0.1uF  [0402]
C32  0.1uF  [0402]
C35  DNS(0402)  [0402]
C36  DNS(0402)  [0402]
C37  DNS(0402)  [0402]
C38  DNS(0402)  [0402]
C39  DNS(0402)  [0402]
C40  DNS(0402)  [0402]
C62  DNS(0402)  [0402]
C67  DNS(0402)  [0402]
DS1  RED LED  [LED-0603]
DS2  YELLOW LED  [LED-0603]
DS3  BLUE LED  [LED-0603]
J12  HEADER 25X2  [HDR25X2]
JP28  B2B-PH-K-S  [CON_B2B_PH_K_SLFSN_JST]
Q2  MMBT3904/SOT  [TRA-SOT23]
Q3  MMBT3904/SOT  [TRA-SOT23]
R19  1K  [0402]
R20  0ohm  [0402]
R22  0ohm  [0402]
R23  10K  [0402]
R24  100K  [0402]
R25  DNS  [0402]
R26  560  [0402]
R27  1K  [0402]
R28  470  [0402]
R29  1M  [0402]
R30  1K  [0402]
R31  1M  [0402]
R32  10K  [0402]
R69  10K  [0402]
R71  10K  [0402]
R84  DNS  [0402]
R85  DNS  [0402]
R95  DNS  [0402]
R96  DNS  [0402]
R97  DNS  [0402]
S2  SWI-SM-PTS645  [SWI-SM-PTS645]
S3  SWI-SM-PTS645  [SWI-SM-PTS645]
SW1  SW DIP-3  [SW-DIP-219-3]
U3  LIS3DH  [LGA-16-3X3]
U4  ENS210-LQFM  [SON-04-2X2MM]
U13  DNS  [USON-8-2X3-EP]
U15  DNS  [SOT23-6]
sheet 07. Harvesting
C63  0.33uF  [1206]
C76  10uF  [0402]
C77  47uF  [1206]
C78  DNS  [1206]
C79  10uF  [0402]
C80  47uF  [1206]
C81  DNS  [1206]
C82  DNS  [1206]
C83  47uF  [1206]
D1  BAT54S-7-F  [TRA-SOT23]
D7  SS12  [SMA_CASE_403AE]
J19  OSTVN02A150  [CONN-OSTVN02A150]
J25  OSTVN02A150  [CONN-OSTVN02A150]
J29  HEADER-3  [HDR1X3]
J31  HEADER-3  [HDR1X3]
JP30  JUMPER-2  [HDR1X2]
JP31  JUMPER-2  [HDR1X2]
JP32  JUMPER-2  [HDR1X2]
L13  47uH  [L_MPIT6028]
Q9  YJL2312A  [SOT23]
R120  0ohm  [0402]
R122  1K  [0402]
sheet 08. MK22
C41  0.1uF  [0402]
C42  0.1uF  [0402]
C43  0.1uF  [0402]
C44  0.1uF  [0402]
C45  0.1uF  [0402]
C46  DNS(0402)  [0402]
DS4  GREEN LED  [LED-0603]
J15  FCI 10118194-0001LF  [10118194-0001LF]
J27  DNS  [MOLEX-105133-0031]
R38  0ohm  [0402]
R39  0ohm  [0402]
R40  0ohm  [0402]
R41  0ohm  [0402]
R42  0ohm  [0402]
R43  0ohm  [0402]
R45  10K  [0402]
R46  33  [0402]
R47  33  [0402]
R48  0ohm  [0402]
R49  0ohm  [0402]
R50  0ohm  [0402]
R51  0ohm  [0402]
R66  0ohm  [0402]
R67  10K  [0402]
R83  10K  [0402]
R118  0ohm  [0402]
R123  100K  [0402]
TC1  DNS(TC2030-IDC)  [CON-TC2030-IDC]
TP6  TP  [TESTPAD50]
TP7  TP  [TESTPAD50]
TP8  TP  [TESTPAD50]
TP9  TP  [TESTPAD50]
TP10  TP  [TESTPAD50]
TP11  TP  [TESTPAD50]
TP13  TP  [TESTPAD50]
TP14  TP  [TESTPAD50]
TP15  TP  [TESTPAD50]
TP16  TP  [TESTPAD50]
U5  NSP4201MR6  [TSOP-6]
U6  MK22FN128VLH10  [LQFP-64-10X10-0.5MM]
U22  74LVC1G08GV,125  [SOT23-5]
sheet 09. Power
BT2  DNS  [BAT-HOLDER-2032]
C47  DNS(0402)  [0402]
C48  1.0uF  [0402]
C49  1.0uF  [0402]
C50  1000pF  [0402]
C51  1.0uF  [0402]
C52  1.0uF  [0402]
C53  DNS(0402)  [0402]
C54  DNS(0402)  [0402]
C55  DNS(0402)  [0402]
C61  0.01uF  [0402]
FD1  TEST POINT  [FID-G]
FD2  TEST POINT  [FID-G]
FD3  TEST POINT  [FID-G]
FD4  TEST POINT  [FID-G]
J21  HEADER-3  [HDR1X3]
J22  DNS(HDR1X3)  [HDR1X3]
J23  HEADER-3  [HDR1X3]
J28  HEADER-3  [HDR1X3]
JP12  DNS(HDR1X2)  [HDR1X2]
JP13  DNS(HDR1X2)  [HDR1X2]
JP14  DNS(HDR1X2)  [HDR1X2]
JP15  DNS(HDR1X2)  [HDR1X2]
JP16  DNS(HDR1X2)  [HDR1X2]
JP24  DNS(HDR1X2)  [HDR1X2]
MT1  TEST POINT  [HOLE-250R125]
MT2  TEST POINT  [HOLE-250R125]
MT3  TEST POINT  [HOLE-250R125]
MT4  TEST POINT  [HOLE-250R125]
MT5  TEST POINT  [HOLE-250R125]
MT6  TEST POINT  [HOLE-250R125]
R53  0ohm  [0402]
R54  DNS  [0402]
R57  0ohm  [0402]
R58  27K  [0402]
R59  10K  [0402]
R60  DNS  [0402]
R61  DNS  [0402]
R62  DNS  [0402]
R73  0ohm  [0402]
R77  0ohm  [0402]
R78  0ohm  [0402]
R104  DNS  [0402]
SB136  Short  [SB]
SB137  Short  [SB]
SB138  Short  [SB]
SB140  Short  [SB]
SB141  Short  [SB]
SB147  Short  [SB]
TP19  TP-WHT  [TESTPIN]
TP20  TP-WHT  [TESTPIN]
TP21  TP-WHT  [TESTPIN]
TP22  TP-WHT  [TESTPIN]
VR1  MIC5255-3.3YD5  [SOT23-5]
VR2  AP2127K-ADJTRG1  [SOT23-5]
VR3  DNS  [SOT23-5]
sheet 10. VDDIO-VCCIO Tracking
C74  1.0uF  [0402]
C75  0.1uF  [0402]
Q5  BSS84PW  [SOT-323]
R108  100K  [0402]
R109  93.1K  [0402]
R110  50  [0402]
R111  DNS  [0402]
R112  0ohm  [0402]
R113  0ohm  [0402]
U17  MCP6001  [SC70]
U18  TMUX1237  [SC70-6]
U19  MCP6001  [SC70]
U20  MCP6001  [SC70]
U21  MCP6001  [SC70]

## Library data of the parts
C1 C10 C11 C17 C48 C49 C51 C52 C64 C74 = SMALL_CAP: Manufacture_Name: MURATA; Manufacture_Part_Number: GRT155R61E105ME01D; Part Number: 01-2000007; Price: 0.003; Datasheet: https://www.digikey.com/product-detail/en/murata-electronics-north-america/GRT155R61E105ME01D/490-12264-1-ND/5416965
C2-C7 C14 C76 C79 = SMALL_CAP: Manufacture_Name: MURATA; Manufacture_Part_Number: GRM155R60J106ME15D; Part Number: 01-2000011; Price: 0.00378; Datasheet: https://www.digikey.com/product-detail/en/murata-electronics-north-america/GRM155R60J106ME15D/490-13238-1-ND/5877446
C8 C77 C80 C83 = SMALL_CAP: Manufacture_Name: SAMSUNG; Manufacture_Part_Number: CL31A476MQHNNNE; Part Description: CAP CER 47UF 6.3V X5R 1206; Part Number: 01-4000001; Price: 0.0189; Datasheet: https://www.digikey.tw/zh/products/detail/samsung-electro-mechanics/CL31A476MQHNNNE/3886825?s=N4IgTCBcDaIMIBkDMBGAggFgOwDYCyAigBIByZAoiALoC%2BQA
C12 = SMALL_CAP: Manufacture_Name: MURATA; Manufacture_Part_Number: GRM185R60J106ME15J; Part Number: 01-3000002; Price: 0.0038; Datasheet: https://www.digikey.com/en/products/detail/murata-electronics/GRM185R60J106ME15J/7363093
C13 C78 C81 C82 = SMALL_CAP
C22 C24 C29 C35-C40 C46 C47 C53-C55 C62 C67 C68 = SMALL_CAP: Part Number: 01-2000016
J3 J21 J23 J26 J28 J29 J31 = HEADER_3: Manufacture_Name: AMPHENOL ICC (FCI); Manufacture_Part_Number: 68000-103HLF; Part Number: 08-0000003; Datasheet: https://www.digikey.tw/en/products/detail/amphenol-cs-fci/68000-103HLF/2023309?s=N4IgTCBcDaIGwA4AMKC0BGJBmAEgGQDEQBdAXyA
JP1 JP5 JP8 JP12-JP16 JP24 = JUMPER-2: Part Number: 08-0000019
JP11 JP25-JP27 JP30-JP32 = JUMPER-2: Manufacture_Name: AMPHENOL ICC (FCI); Manufacture_Part_Number: 68000-102HLF; Part Number: 08-0000002; Price: 0.0066; Datasheet: https://www.digikey.com/products/en?keywords=68000-102HLF
L1 = INDUCTOR: Manufacture_Name: MURATA; Manufacture_Part_Number: LQM2MPN3R3NG0L; Part Number: 02-4000013; Price: 0.025; Datasheet: https://www.digikey.com/en/products/detail/murata-electronics/LQM2MPN3R3NG0L/4359169?s=N4IgTCBcDaIDoBcAEAZAigWTBgCgOwGYAlAgOQHEAGFEAXQF8g
R6 = SMALL_R1: Manufacture_Name: YAGEO; Manufacture_Part_Number: RC0402FR-071RL; Part Description: RES 1 OHM 1% 1/16W 0402; Part Number: 03-2000032; Price: 0.0002; Datasheet: https://www.digikey.com/product-detail/en/yageo/RC0402FR-071RL/311-1.00LRCT-ND/729461
R8 R23 R32 R45 R59 R67 R69 R71 R83 = SMALL_R1: Manufacture_Name: WALSIN; Manufacture_Part_Number: WR04X1002FTL; Part Description: RES 10K OHM 1% 1/16W 0402; Part Number: 03-2000022; Price: 0.0002; Datasheet: https://www.digikey.com/en/products/detail/walsin-technology-corporation/WR04X1002FTL/13241339?s=N4IgTCBcDaIOoCUAMAWAGgRiUsAxAKgDIgC6AvkA
R13 R17 R18 R20 R22 R38-R43 R48-R51 R53 R57 R66 R73 R77 R78 R103 R112 R113 R118 R120 = SMALL_R1: Manufacture_Name: PANASONIC; Manufacture_Part_Number: ERJ-2GE0R00X; Part Number: 03-2000018; Price: 0.0002; Datasheet: https://www.digikey.com/en/products/detail/panasonic-electronic-components/erj-2ge0r00x/146727
R15 R24 R108 R123 = SMALL_R1: Manufacture_Name: YAGEO; Manufacture_Part_Number: RC0402JR-07100KL; Part Number: 03-2000020; Price: 0.0002; Datasheet: https://www.digikey.com/en/products/detail/yageo/RC0402JR-07100KL/726416
S1-S3 = SW-TACT-4P-5: Manufacture_Name: C&K; Manufacture_Part_Number: PTS645SK50SMTR92 LFS; Part Number: 07-0000027; Datasheet: https://www.digikey.com/product-detail/en/c-k/PTS645SK50SMTR92-LFS/CKN9087CT-ND/1146813
SB2 SB9 SB131 SB136-SB138 SB140 SB141 SB143 SB147 = SB: Part Number: 03-1000004
SB6 = SB: Part Number: 03-1000006
TP1 TP19-TP22 TP25 = TP: Manufacture_Name: KEYSTONE ELECTRONICS; Manufacture_Part_Number: 36-5012-ND; Part Number: 08-0000007; Datasheet: https://www.digikey.com/product-detail/en/keystone-electronics/5012/36-5012-ND/255334
TP3-TP5 TP23 = TP: Manufacture_Name: KEYSTONE ELECTRONICS; Manufacture_Part_Number: 36-5011-ND; Part Number: 08-0000006; Datasheet: https://www.digikey.com/product-detail/en/keystone-electronics/5011/36-5011-ND/255333
U1 = ATM3332-202_1: Manufacture_Name: Atmosic; Manufacture_Part_Number: ATM3430E-2WCAQN; Part Description: ATM3430e, QFN-56-7x7-0.4MM-EP5.2MM, EH, 1536/256K; Part Number: 04-0000011
Y1 = XTAL: Manufacture_Name: SEIKO; Manufacture_Part_Number: SC20S-7PF20PPM; Part Number: 06-0000018; Price: 0.065; Datasheet: https://www.digikey.com/short/797qhnc0
Y2 = XTAL-OSC-4P_0: Manufacture_Name: Hosonic; Manufacture_Part_Number: E1SB16E00001KE; Part Number: 06-0000075; Price: 0.043; Datasheet: https://drive.google.com/drive/folders/1THAUNzENGgR3SJ0kmd_V7woV18_ClvpD
C31 C32 C41-C45 C56-C60 C72 = SMALL_CAP: Manufacture_Name: TAIYO-YUDEN; Manufacture_Part_Number: TMK105BJ104KV-F; Part Number: 01-2000003; Price: 0.0013; Datasheet: https://www.digikey.com/en/products/detail/taiyo-yuden/TMK105BJ104KV-F/1004044
R29 R31 R72 R74 R98 R99 = SMALL_R1: Manufacture_Name: YAGEO; Manufacture_Part_Number: RC0402JR-071ML; Part Number: 03-2000030; Price: 0.0002; Datasheet: https://www.digikey.com/product-detail/en/yageo/RC0402JR-071ML/311-1.0MJRCT-ND/729356
R25 R54 R60-R62 R79 R84 R85 R95-R97 R104 R111 = SMALL_R1: Part Number: 03-2000042
TP6-TP11 TP13-TP16 TP24 = TP_0: Part Number: 09-0000005
U7 U9 U10 U16 = NX3DV2567: Manufacture_Name: NXP; Manufacture_Part_Number: NX3DV2567GU115; Part Number: 05-0000007; Datasheet: https://www.mouser.com/ProductDetail/NXP-Semiconductors/NX3DV2567GU115?qs=67TfscD5Pafw%252BgjlE0rl%2Fg%3D%3D
U11 U12 = NX3DV2567
C18 = SMALL_CAP: Manufacture_Name: PANASONIC; Manufacture_Part_Number: ERJ-2GE0R00X; Part Number: 01-2000027; Price: 0.0002; Datasheet: https://www.digikey.com/en/products/detail/panasonic-electronic-components/erj-2ge0r00x/146727
C20 = SMALL_CAP: Manufacture_Name: JOHANSON; Manufacture_Part_Number: 500R07S1R0BV4T; Part Number: 01-2000006; Price: 0.001; Datasheet: https://www.digikey.com/en/products/detail/johanson-technology-inc/500R07S1R0BV4T/1561521?s=N4IgTCBcDaIKwAYECUEHYDKBGVAhAagCwAqIAugL5A
C21 = SMALL_CAP: Manufacture_Name: JOHANSON; Manufacture_Part_Number: QSCF500Q1R5B1GV001T; Part Description: CAP CER 1.5PF  ∮0.1pF 50V C0G/NP0 0402; Part Number: 01-2000035; Price: 0.001; Datasheet: https://www.digikey.com/en/products/detail/johanson-technology-inc/QSCF500Q1R5B1GV001T/1561525?s=N4IgTCBcDaIDoBcAEBWADGgSmg7AZQEZMUAhANQBYAVEAXQF8g
C23 C65 = SMALL_CAP: Manufacture_Name: JOHANSON; Manufacture_Part_Number: 500R07S100JV4T; Part Number: 01-2000010; Price: 0.001; Datasheet: https://www.digikey.com/en/products/detail/johanson-technology-inc/500R07S100JV4T/1786715
C25 = SMALL_CAP: Manufacture_Name: TDK; Manufacture_Part_Number: MHQ1005P2N9BT000; Part Description: FIXED IND 2.9NH ∮0.1nH 0.9A 80 MOHM SMD; Part Number: 02-2000025; Price: 0.0035; Datasheet: https://www.digikey.tw/zh/products/detail/tdk-corporation/MHQ1005P2N9BT000/5167620?s=N4IgTCBcDaILIAkCKBGADGgrABTAOQE4AhAFQzRAF0BfIA
C26 C30 = SMALL_CAP: Manufacture_Name: JOHANSON; Manufacture_Part_Number: QSCF500Q2R7B1GV001T; Part Description: CAP CER 2.7PF  ∮0.1pF 50V C0G/NP0 0402; Part Number: 01-2000036; Price: 0.001; Datasheet: https://www.digikey.tw/zh/products/detail/johanson-technology-inc/QSCF500Q2R7B1GV001T/1561530?s=N4IgTCBcDaIIoGUDCAxArABg3MAlA7AEICMA4gGpbEAqIAugL5A
C27 C28 = SMALL_CAP: Manufacture_Name: JOHANSON; Manufacture_Part_Number: 500R07N101JV4T; Part Description: CAP CER 100PF 50V  ∮5% C0G/NP0 0402; Part Number: 01-2000028; Price: 0.001; Datasheet: https://www.mouser.tw/ProductDetail/Johanson-Dielectrics/500R07N101JV4T?qs=yCnrNFeXz%252BgpESXZqTmimw%3D%3D
C66 = SMALL_CAP: Part Number: 01-1000002
J4-J6 = SMA_SL: Manufacture_Name: CINCH CONNECTIVITY SOLUTIONS JOHNSON; Manufacture_Part_Number: 142-0701-801; Part Number: 08-0000005; Price: 1.03; Datasheet: https://www.digikey.com/product-detail/en/cinch-connectivity-solutions-johnson/142-0701-801/J502-ND/35280
L3 L5 = INDUCTOR: Part Number: 02-2000004
L4 = INDUCTOR: Manufacture_Name: TDK; Manufacture_Part_Number: MHQ1005P6N8JT000; Part Description: FIXED IND 6.8NH ∮5% 0.7A 140 MOHM SMD; Part Number: 02-2000026; Price: 0.0035; Datasheet: https://www.digikey.tw/zh/products/detail/tdk-corporation/MHQ1005P6N8JT000/3910212
L6 L9 = INDUCTOR: Manufacture_Name: MURATA; Manufacture_Part_Number: LQW15AN10NG8ZD; Part Description: FIXED IND 10NH ∮2% 1.4A 81MOHM SMD; Part Number: 02-2000027; Price: 0.073; Datasheet: https://www.digikey.com/en/products/detail/murata-electronics/LQW15AN10NG8ZD/6798756?s=N4IgTCBcDaIDYEcDuBGArAQwHYoAxYHMAOALwBMQBdAXyA
L7 L10 = INDUCTOR: Manufacture_Name: MURATA; Manufacture_Part_Number: LQW15AN12NG8ZD; Part Description: FIXED IND 12NH ∮2% 1.24A 93MOHM SMD; Part Number: 02-2000028; Price: 0.073; Datasheet: https://www.digikey.com/en/products/detail/murata-electronics/LQW15AN12NG8ZD/6798760?s=N4IgTCBcDaIDoBcAEAZAigdQIwFYCCAclmAQOIAcAWgCIgC6AvkA
L8 = INDUCTOR: Manufacture_Name: MURATA; Manufacture_Part_Number: LQW15AN15NG8ZD; Part Description: FIXED IND 15NH ∮2% 1.15A 111MOHM SMD; Part Number: 02-2000029; Price: 0.073; Datasheet: https://www.digikey.com/en/products/detail/murata-electronics/LQW15AN15NG8ZD/6798766?s=N4IgTCBcDaIDYEcDuBGArAQwHbqwcwA4AvAExAF0BfIA
L11 = INDUCTOR: Manufacture_Name: TDK; Manufacture_Part_Number: MHQ1005P3N0BT000; Part Description: FIXED IND 3.0NH ∮0.1nH 900MA 80 MOHM SMD; Part Number: 02-2000021; Price: 0.0035; Datasheet: https://www.digikey.com/en/products/detail/tdk-corporation/MHQ1005P3N0BT000/4742526?s=N4IgTCBcDaILIAkCKBGADGgrABQMwDk0AhAFQzRAF0BfIA
L12 = INDUCTOR: Manufacture_Name: TDK; Manufacture_Part_Number: MHQ1005P2N7BT000; Part Description: FIXED IND 2.7NH ∮0.1nH 1A 70 MOHM SMD; Part Number: 02-2000002; Price: 0.0035; Datasheet: https://www.digikey.com/en/products/detail/tdk-corporation/mhq1005p2n7bt000/4742525
DS1 = LED: Manufacture_Name: WURTH ELEKTRONIK; Manufacture_Part_Number: 150060RS75000; Part Number: 06-0000016; Price: 0.0083; Datasheet: https://www.digikey.com/en/products/detail/w%C3%BCrth-elektronik/150060RS75000/4489901
DS2 = LED: Manufacture_Name: WURTH ELEKTRONIK; Manufacture_Part_Number: 150060YS75000; Part Number: 06-0000017; Price: 0.0083; Datasheet: https://www.digikey.com/en/products/detail/w%C3%BCrth-elektronik/150060YS75000/4489909
DS3 = LED: Manufacture_Name: WURTH ELEKTRONIK; Manufacture_Part_Number: 150060BS75000; Part Number: 06-0000014; Price: 0.0083; Datasheet: https://www.digikey.com/en/products/detail/w%C3%BCrth-elektronik/150060BS75000/4489893
J12 = HEADER_25X2: Manufacture_Name: AMPHENOL ICC (FCI); Manufacture_Part_Number: 67996-150HLF; Part Number: 08-0000004; Datasheet: https://www.digikey.com/products/en?keywords=67996-150HLF
JP28 = B2B-PH-K-SLFSN: Manufacture_Name: JST; Part Description: CONN HEADER VERT 2POS 2MM; Part Number: 08-0000044; Datasheet: https://www.jst-mfg.com/product/pdf/eng/ePH.pdf
Q2 Q3 = MMBT3904_SOT: Manufacture_Name: NEXPERIA; Manufacture_Part_Number: PMBT3904-215; Part Number: 06-0000022; Datasheet: https://www.digikey.com/en/products/detail/nexperia-usa-inc/PMBT3904-215/763515
R19 R27 R30 R122 = SMALL_R1: Manufacture_Name: WALSIN; Manufacture_Part_Number: WR04X1001FTL; Part Description: RES 1K OHM 1% 0402; Part Number: 03-2000028; Price: 0.0002; Datasheet: https://www.digikey.com/en/products/detail/walsin-technology-corporation/WR04X1001FTL/13240628?s=N4IgTCBcDaIOoCUAMAWAGgRiUjAxAKgDIgC6AvkA
R26 = SMALL_R1: Manufacture_Name: YAGEO; Manufacture_Part_Number: RC0402JR-07560RL; Part Number: 03-2000015; Price: 0.0002; Datasheet: https://www.digikey.com/en/products/detail/yageo/RC0402JR-07560RL/726492?s=N4IgTCBcDaIEoGEAMAWJYBScC0SDsArAGxJwAyIAugL5A
R28 = SMALL_R1: Manufacture_Name: YAGEO; Manufacture_Part_Number: RC0402JR-07470RL; Part Number: 03-2000012; Price: 0.0002; Datasheet: https://www.digikey.com/en/products/detail/yageo/RC0402JR-07470RL/726482?s=N4IgTCBcDaIEoGEAMAWJYBScC0SDsKeScAMiALoC%2BQA
SW1 = SW_DIP-3: Manufacture_Name: CTS Electrocomponents; Manufacture_Part_Number: 219-3MSTR; Part Description: SWITCH SLIDE DIP SPST 100MA 20V; Part Number: 08-0000018; Price: 0.486; Datasheet: https://www.digikey.com/en/products/detail/cts-electrocomponents/219-3MSTR/5224026
U3 = LIS3DHTR_0: Manufacture_Name: STMicroelectronics; Part Description: ACCEL 2-16G I2C/SPI 16LGA; Part Number: 05-0000003; Price: 0.84; Datasheet: https://www.digikey.com/en/products/detail/stmicroelectronics/LIS3DH/2334335
U4 = ENS210-LQFM_2: Manufacture_Name: SCIOSENSE; Part Number: 05-0000005; Datasheet: https://www.mouser.com/ProductDetail/ScioSense/ENS210-LQFM?qs=Zcin8yvlhnP3xLiFn26B1g%3D%3D
U13 = LM258DRG3_0
U15 = 24AA014_0
C63 = SMALL_CAP: Manufacture_Name: SAMSUNG; Manufacture_Part_Number: CL31B334KACNNNC; Part Description: CAP CER 0.33UF 25V X7R 1206; Part Number: 01-4000007; Datasheet: https://www.digikey.tw/zh/products/detail/samsung-electro-mechanics/CL31B334KACNNNC/3887498?s=N4IgTCBcDaIMwEYBCc4BYDSBBAwgOQJxAF0BfIA
D1 = DIODE_1A2C3COM: Manufacture_Name: DIODES; Manufacture_Part_Number: BAT54CT-7-F; Part Description: DIODE ARR SCHOT 30V 200MA SOT523; Part Number: 06-0000076; Price: 0.013; Datasheet: https://www.digikey.tw/zh/products/detail/diodes-incorporated/BAT54CT-7-F/717703
D7 = TMP_0: Manufacture_Name: Yangzhou Yangjie Electronic; Manufacturer_Name: ON SEMI; Part Description: DIODE SCHOTTKY 20V 1A DO214AC; Part Number: 06-0000077; Price: 0.012; Datasheet: https://www.21yangjie.com/pdf/zlqj/xtjejg/SS12A%20THRU%20SS120A.pdf
J19 J25 = CON2: Manufacture_Name: On Shore Technology Inc.; Part Description: TERM BLK 2P SIDE ENT 2.54MM PCB; Part Number: 07-0000010; Price: 0.287; Datasheet: https://www.digikey.com/en/products/detail/on-shore-technology-inc/OSTVN02A150/1588862?s=N4IgTCBcDaIPIGUAqA1AcgBjAQQIwFYMQBdAXyA
L13 = INDUCTOR: Manufacture_Name: MICROGATE; Manufacture_Part_Number: MPIT5020-470M-LF; Manufacturer_Name: MICROGATE; Manufacturer_Part_Number: MPIT6028-680M31-LF; Part Number: 02-4000009; Price: 0.046; Datasheet: https://www.lcsc.com/product-detail/Power-Inductors_microgate_C696476.html
Q9 = MPF990_0: Manufacture_Name: Yangzhou Yangjie Electronic; Manufacturer_Name: YANGJIE; Part Description: MOSFET N-CH 20V 6.8MA SOT-23; Part Number: 06-0000065; Price: 0.024; Datasheet: https://www.21yangjie.com/pdf/mosfet/YJL2312A.pdf
DS4 = LED: Manufacture_Name: WURTH ELEKTRONIK; Manufacture_Part_Number: 150060GS75000; Part Number: 06-0000015; Price: 0.0043; Datasheet: https://www.digikey.com/en/products/detail/w%C3%BCrth-elektronik/150060GS75000/4489898?s=N4IgTCBcDaIIwFYAMSBsSDiBlA7MlIAugL5A
J15 = USB_CONN_1_v2: Manufacture_Name: AMPHENOL ICC (FCI); Part Number: 07-0000004; Datasheet: https://www.digikey.com/en/products/detail/amphenol-icc-fci/10118194-0001LF/2785389
J27 = USB_CONN_1
R46 R47 = SMALL_R1: Manufacture_Name: YAGEO; Manufacture_Part_Number: RC0402JR-0733RL; Part Number: 03-2000003; Price: 0.0002; Datasheet: https://www.digikey.com/en/products/detail/yageo/RC0402JR-0733RL/726467?s=N4IgTCBcDaIDoBcAEAlAwgBgCwbAKRQFoMB2AZjJQBkQBdAXyA
TC1 = TC2030-IDC: Part Number: 08-0000038
U5 = NSP4201MR6_0: Manufacture_Name: onsemi; Manufacture_Part_Number: NSP4201MR6T1G; Part Description: TVS DIODE 5VWM 12VC 6TSOP; Part Number: 05-0000023; Datasheet: https://www.digikey.com/product-detail/en/on-semiconductor/NSP4201MR6T1G/NSP4201MR6T1GOSCT-ND/7556459
U6 = MK22FN128VLH10_0: Manufacture_Name: NXP; Part Description: IC MCU 32BIT 128KB FLASH 64LQFP; Part Number: 05-0000004; Price: 4.64; Datasheet: https://www.digikey.com/en/products/detail/nxp-usa-inc/MK22FN128VLH10/4800173
U22 = 54AS00_1: Manufacture_Name: NEXPERIA; Part Description: AND Gate IC 1 Channel SC-74A, 1.65~6.5V; Part Number: 05-0000034; Datasheet: https://www.digikey.com/en/products/detail/nexperia-usa-inc/74lvc1g08gv-125/1231422
BT2 = BAT
C50 = SMALL_CAP: Manufacture_Name: MURATA; Manufacture_Part_Number: GRM155R72A102KA01D; Part Description: CAP CER 1000PF 100V ∮10% X7R 0402; Part Number: 01-2000026; Price: 0.001; Datasheet: https://www.digikey.com/en/products/detail/murata-electronics/GRM155R72A102KA01D/2610953?s=N4IgTCBcDaIOICUCyBGArGhB2MBBFADGANK4EoAiIAugL5A
C61 = SMALL_CAP: Manufacture_Name: TDK; Manufacture_Part_Number: CGA2B3X7R1H103K050BB; Part Number: 01-2000001; Price: 0.0016; Datasheet: https://www.digikey.com/en/products/detail/tdk-corporation/CGA2B3X7R1H103K050BB/2672786
FD1-FD4 = TEST_POINT: Part Number: 09-0000007
J22 = HEADER_3: Part Number: 08-0000020
MT1-MT6 = TEST_POINT: Part Number: 09-0000006
R58 = SMALL_R1: Manufacture_Name: YAGEO; Manufacture_Part_Number: RC0402FR-0727KL; Part Number: 03-2000033; Price: 0.0002; Datasheet: https://www.digikey.com/en/products/detail/yageo/RC0402FR-0727KL/726574
VR1 = VAR_REG: Manufacture_Name: MICREL; Part Description: IC REG LIN 3.3V 150MA TSOT23-5; Part Number: 06-0000037; Price: 0.48; Datasheet: https://www.digikey.com/en/products/detail/microchip-technology/MIC5255-3-3YD5-TR/1030949?s=N4IgTCBcDaILIEkDCBWMKUFoDMA6bAmgCIogC6AvkA
VR2 = VAR_REG: Manufacture_Name: DIODES; Part Description: IC REG LIN POS ADJ 300MA SOT23-5; Part Number: 06-0000032; Price: 0.094; Datasheet: https://www.digikey.com/en/products/detail/diodes-incorporated/AP2127K-ADJTRG1/4470788?s=N4IgTCBcDaIIIAUwEYwHYDSBaOARAUgCoBKA4siALoC%2BQA
VR3 = VAR_REG
C75 = SMALL_CAP: Manufacture_Name: TAIYO-YUDEN; Manufacture_Part_Number: TMK105BJ104KV-F; Part Number: 01-2000003; Price: 0.0013; Vendor: TAIYO-YUDEN; Datasheet: https://www.digikey.com/en/products/detail/taiyo-yuden/TMK105BJ104KV-F/1004044
Q5 = BSS84_SOT_0: Manufacture_Name: INFINEON; Manufacture_Part_Number: BSS84PWH6327XTSA1; Part Description: PMOS 60 V 150mA (Ta) 300mW (Ta) SOT323; Part Number: 06-0000057; Datasheet: https://www.digikey.com/en/products/detail/infineon-technologies/BSS84PWH6327XTSA1/5410126
R109 = SMALL_R1: Manufacture_Name: YAGEO; Manufacture_Part_Number: RC0402FR-0793K1L; Part Description: RES 93.1K OHM 1% 0402; Part Number: 03-2000071; Price: 0.0002; Datasheet: https://www.digikey.com/en/products/detail/yageo/RC0402FR-0793K1L/5281120?s=N4IgTCBcDaIEoGEAMAWJYBicC0SDsAnAMwDSAjADIgC6AvkA
R110 = SMALL_R1: Manufacture_Name: YAGEO; Manufacture_Part_Number: RC0402JR-0750RL; Part Description: RES 50 OHM 5% 1/16W 0402; Part Number: 03-2000072; Price: 0.0002; Datasheet: https://www.digikey.com/en/products/detail/yageo/RC0402JR-0750RL/5917787?s=N4IgTCBcDaIEoGEAMAWJYBScC0SDsArEnADIgC6AvkA
U17 U19-U21 = MCP6001: Manufacture_Name: Microchip Technology; Manufacture_Part_Number: MCP6001T-E/LT; Part Description: IC OPAMP GP 1 CIRCUIT SOT23-5; Part Number: 05-0000021; Datasheet: https://www.digikey.com/en/products/detail/microchip-technology/MCP6001T-E-LT/683192
U18 = TMUX1237: Manufacture_Name: Texas Instruments; Manufacture_Part_Number: TMUX1237DCKR; Part Description: IC SWITCH SPDT X 1 4.5OHM SC70-6; Part Number: 05-0000022; Datasheet: https://www.digikey.com/en/products/detail/texas-instruments/tmux1237dckr/12165109

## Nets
1.8V: J22.3 R60.2
3.0V: J21.1 J22.1 R57.2
3.3V: C39.2 C40.1 C45.1 J12.26 R26.2 R28.2 R53.2 R109.1 U6.7(USBVDD)
AVDD1: C12.1 C13.1 R6.1 U1.1(AVDD1)
AVDD1P: C4.1 JP5.1 SB9.1 U1.25(AVDD1P)
AVDDPA: J3.2 R13.1
DVDD1: C1.1 JP1.2 SB2.2 U1.30(DVDD1)
DVDD1P: C3.1 JP1.1 SB2.1 U1.27(DVDD1P)
GND_SIGNAL: BT2.2(NEG) C1.2 C2.2 C3.2 C4.2 C5.2 C6.2 C7.2 C8.1 C10.2 C11.2 C12.2 C13.2 C14.2 C17.2 C20.1 C21.1 C22.2 C24.1 C25.1 C29.1 C30.1 C31.2 C32.2 C35.1 C36.2 C37.1 C38.2 C39.1 C40.2 C41.2 C42.2 C43.2 C44.2 C45.2 C46.2 C48.1 C49.1 C51.1 C52.1 C54.1 C55.1 C56.2 C57.2 C58.2 C59.2 C60.2 C61.1 C62.2 C64.2 C66.2 C67.1 C68.2 C72.2 C74.2 C75.2 C76.2 C77.2 C78.1 C79.2 C80.1 C81.1 C82.1 C83.1 DS1.1(CATHODE) J4.2(GND1) J4.3(GND2) J5.2(GND1) J5.3(GND2) J6.2(GND1) J6.3(GND2) J12.1 J12.27 J15.5(GND) J15.S1(CASE) J15.S2(CASE) J15.S3(CASE) J15.S4(CASE) J15.S5(CASE) J15.S6(CASE) J19.2 J25.2 J27.5(GND) J27.S1(CASE) J27.S2(CASE) J27.S3(CASE) JP32.2 L5.2 L6.2 MT1.1 MT2.1 MT3.1 MT4.1 MT5.1 MT6.1 Q2.2(E) Q3.2(E) Q9.2(SOURCE) R8.1 R15.1 R25.1 R29.1 R32.1 R45.1 R59.2 R62.2 R72.1 R74.1 R79.1 R98.1 R99.1 R103.2 R108.2 R111.2 R123.2 S3.3 S3.4 SB6.2 TC1.5(GND) TP3.1(TP) TP4.1(TP) TP5.1(TP) TP23.1(TP) U1.57(EGND) U3.5(GND) U3.10(RES) U3.12(GND_1) U4.4(VSS) U4.5(VSS_1) U5.2(GND) U6.4(VSS) U6.15(VREFL) U6.16(VSSA) U6.31(VSS) U6.32(PTA18) U6.33(PTA19) U6.47(VSS) U7.6(GND) U9.6(GND) U10.6(GND) U11.6(GND) U12.6(GND) U13.4(GND) U13.9(EP) U15.2(VSS) U15.4(A1) U16.6(GND) U17.2 U18.5(S6) U19.2 U20.2 U21.2 U22.3(GND) VR1.2(GND) VR2.2(GND) VR3.2(GND) Y2.2(NC) Y2.4(NC)
VBAT: C7.1 J23.1 J26.1 J28.3 U1.20(VBAT)
VBATLI: C64.1 SB147.1 U1.28(VBATLI)
VCC_BIDS: C62.1 R20.2 R22.2 R23.1 R24.1 R31.2 R69.2 R71.2 R84.2 R85.2 R97.2 S2.3 S2.4 U10.15(1Y1) U15.6(VCC)
VCC_F: C67.2 R95.1 R96.1 U11.15(1Y1) U13.8(VCC)
VCC_USB: C49.2 C52.2 C55.2 C75.1 DS4.2(ANODE) J15.1(VBUS) J27.1(VBUS) Q5.2(S) TP21.1(TP) U5.5(VP) U17.5 U18.2(VDD) U19.5 U20.5 U21.5 VR1.1(VIN) VR1.3(EN) VR2.1(VIN) VR2.3(EN) VR3.1(VIN) VR3.3(EN)
VCCIO: C35.2 C36.1 C37.2 C38.1 C56.1 C57.1 C58.1 C59.1 C60.1 C72.1 J12.2 J12.50 J26.3 JP8.1 JP11.1 JP25.1 JP27.1 JP28.1 R78.2 R104.2 R113.2 U7.14(VCC) U9.14(VCC) U10.14(VCC) U11.14(VCC) U12.14(VCC) U16.14(VCC)
VCCIO_K22: C41.1 C42.1 C43.1 C44.1 JP14.1 SB138.1 TC1.1(VCC) U6.3(VDD) U6.13(VDDA) U6.14(VREFH) U6.21(VBAT) U6.26(PTA4/LLWU_P3) U6.30(VDD) U6.48(VDD) U22.5(VCC)
VDDIO: C10.1 C11.1 JP13.1 JP24.1 R112.1 SB137.1 U1.8(VDDIO) U1.39(VDDIO)
VDDIO_FLASH: JP16.1 SB141.1 U11.16(1Z)
VDDIO_SENS: JP15.1 SB140.1 U10.16(1Z)
VDDIOP: C6.1 J3.1 J23.3 JP26.2 U1.24(VDDIOP)
BBOOT: R118.1 U9.1(1Y0)
BENIGN_BOOT: R66.1 R123.1 U22.1(A)
BUTTON_1: JP28.2 R29.2 S2.1 S2.2 SB131.2
BUTTON_2: R31.1 S3.1 S3.2 U16.15(1Y1)
DM: R46.1 U6.6(USB0_DM)
DP: R47.1 U6.5(USB0_DP)
FLASH_CS_L: R95.2 U11.7(3Y1) U13.1(CS#)
FLASH_RESET_L: R96.2 U11.3(2Y1) U13.7(RESET#)
FLASH_SCLK: U11.11(4Y1) U13.6(SCLK)
FLASH_SIO0: U12.3(2Y1) U13.5(SI/SIO0)
FLASH_SIO1: U12.7(3Y1) U13.2(SO/SIO1)
FLASH_SIO2: U12.11(4Y1) U13.3(WP#/SIO2)
G_INT: U3.11(INT1) U10.11(4Y1)
HARV1_RFIN_N: L10.2 U1.18(RFHARV_N)
HARV1_RFIN_P: L7.2 U1.17(RFHARV_P)
I2C0_SCK: R71.1 R97.1 U3.4(SCL/SPC) U4.2(SCL) U10.7(3Y1) U15.1(SCL)
I2C0_SDA: R69.1 R84.1 U3.6(SDA/SDI/SDO) U4.3(SDA) U10.3(2Y1) U15.3(SDA)
LED_1: R19.2 U16.3(2Y1)
LED_2: R27.1 U16.7(3Y1)
LED_3: R30.1 U16.11(4Y1)
LIOn_Bat: C82.2 J25.1 J28.1 JP30.2 R122.1
MODE_0: J12.3 SW1.4(B3) U1.34(P11)
MODE_1: J12.6 SW1.5(B2) U1.37(P14)
MODE_2: J12.16 SW1.6(B1) U1.48(P24)
NO_K22: JP11.2 R74.2 R83.1 SB143.1 U7.2(S)
P0: J12.32 U1.5(P0) U9.4(2Z)
P1: J12.33 U1.6(P1) U9.8(3Z)
P2: J12.34 U1.7(P2)
P3: J12.35 U1.9(P3)
P4: J12.36 U1.10(P4) U16.8(3Z)
P5: J12.37 SB131.1 U1.11(P5)
P6: J12.38 U1.12(P6) U16.16(1Z)
P7: J12.39 U1.13(P7) U16.12(4Z)
P8: J12.40 J29.2 U1.14(P8)
P9: J12.41 U1.15(P9)
P10: J12.42 U1.33(P10)
P12: J12.4 U1.35(P12) U7.12(4Z)
P13: J12.5 U1.36(P13) U7.16(1Z)
P15: J12.7 U1.38(P15) U7.4(2Z)
P16: J12.8 U1.40(P16) U10.8(3Z)
P17: J12.9 U1.41(P17) U10.4(2Z)
P18: J12.10 U1.42(P18) U11.12(4Z)
P19: J12.11 U1.43(P19) U11.8(3Z)
P20: J12.12 U1.44(P20) U12.4(2Z)
P21: J12.13 U1.45(P21) U12.8(3Z)
P22: J12.14 U1.46(P22) U12.12(4Z)
P23: J12.15 U1.47(P23) U11.4(2Z)
P25: J12.17 R15.2 U1.49(P25) U9.16(1Z)
P26: J12.21 U1.52(P26) U10.12(4Z)
P27: J12.22 U1.53(P27) U9.12(4Z)
P28: J12.23 U1.54(P28)
P29: J12.24 U1.55(P29) U16.4(2Z)
P30: J12.25 U1.56(P30) U7.8(3Z)
PV_CELL: C14.1 J19.1 JP31.1 TP1.1(TP) U1.19(VHARV)
PWD: J12.49 R8.2 R67.1 S1.1 S1.2 U1.16(PWD)
RFIO: L11.2 U1.2(RFIO)
SWDCLK_K22: R39.1 U9.5(2Y0)
SWDIO_K22: R38.1 U9.9(3Y0)
UART0_CTS_K22: R51.1 U7.13(4Y0)
UART0_RTS_K22: R50.1 U7.1(1Y0)
UART0_RX_K22: R48.1 U7.9(3Y0)
UART0_TX_K22: R49.1 U7.5(2Y0)
UART1_CTS_K22: R43.1 TP7.1(TP)
UART1_RTS_K22: R42.1 TP6.1(TP)
UART1_RX_K22: R40.1 U22.2(B)
UART1_TX_K22: R41.1 U9.13(4Y0)
UART2_CTS_K22: TP11.1(TP) U6.44(PTC1/LLWU_P6)
UART2_RTS_K22: TP10.1(TP) U6.45(PTC2)
UART2_RX_K22: TP8.1(TP) U6.49(PTC4/LLWU_P8)
UART2_TX_K22: TP9.1(TP) U6.46(PTC3/LLWU_P7)
USB_D+: J15.3(D+) J27.3(D+) R47.2 U5.3(IO2) U5.4(IO3)
USB_D-: J15.2(D-) J27.2(D-) R46.2 U5.1(IO1) U5.6(IO4)
USE_FLASH: JP8.2 R79.2 U11.2(S) U12.2(S)
VAUX: C5.1 JP26.1 U1.26(VAUX)
VCOINCELL: BT2.1(POS) J21.3 R104.1
VSTORE: C2.1 C8.2 C68.1 C76.1 C78.2 J3.3 JP32.1 R120.2 TP25.1(TP) U1.22(VSTORE)
WURX_RFIN: C23.1 U1.3(WURX_RFIN)
XTALI_16M: U1.51(XTALO_16M) Y2.1(HOT)
XTALI_32K: SB6.1 U1.32(XTALI_32K) Y1.2
XTALO_16M: U1.50(XTALI_16M) Y2.3(HOT)
XTALO_32K: U1.31(XTALO_32K) Y1.1
N16735640: JP5.2 R6.2 SB9.2
N16873328: L1.1 U1.21(LEXT1)
N16873338: L1.2 U1.23(LEXT2)
N16893506: C17.1 R13.2 U1.4(AVDDPA)
N17095028: C47.2 C48.2 R53.1 R54.1 VR1.5(VOUT)
N17095050: C47.1 C61.2 R54.2 VR1.4(ADJ)
N17095106: J21.2 JP12.2 R73.1 SB136.2
N17095108: J23.2 JP13.2 JP15.2 JP16.2 R77.2 SB137.2 SB140.2 SB141.2
N17095279: C53.2 C54.2 R60.1 R61.1 VR3.5(VOUT)
N17095319: C53.1 R61.2 R62.1 VR3.4(ADJ)
N17095349: J28.2 JP12.1 SB136.1 SB147.2
N17095531: C50.2 C51.2 R57.1 R58.1 VR2.5(VOUT)
N17095557: C50.1 R58.2 R59.1 VR2.4(ADJ)
N17096185: J22.2 JP14.2 JP24.2 R78.1 SB138.2 TP20.1(TP)
N17098002: R103.1 U1.29(RES)
N17100046: R99.2 SB143.2 TP24.1(TP) U9.2(S)
N17100334: JP25.2 R72.2 U10.2(S)
N17101171: C18.2 J4.1(IO)
N17101173: C18.1 C65.2 C66.1 L3.1
N17101183: C20.2 C65.1 L12.1
N17101189: C21.2 L11.1 L12.2
N17101247: C22.1 L3.2
N17101303: J5.1(IO) R17.2
N17101305: C24.2 L4.1 R17.1
N17101311: C23.2 C25.2 L4.2
N17101384: C26.2 C29.2 L5.1 L9.1 R18.2
N17101386: C26.1 C27.2 L6.1
N17101427: C27.1 L7.1 L8.2
N17101464: J6.1(IO) R18.1
N17101492: C28.1 L8.1 L10.1
N17101511: C28.2 C30.2 L9.2
N17102737: DS1.2(ANODE) R19.1
N17102803: C31.1 R20.1 U3.1(VDD_IO) U3.14(Vdd)
N17102805: C32.1 R22.1 U4.1(VDD)
N17102917: DS2.2(ANODE) R26.1
N17102919: DS2.1(CATHODE) Q2.3(C)
N17103005: R23.2 R25.2 U3.7(SDO/SA0)
N17103017: Q2.1(B) R27.2
N17103021: R24.2 U3.8(CS)
N17103073: DS3.2(ANODE) R28.1
N17103075: DS3.1(CATHODE) Q3.3(C)
N17103123: Q3.1(B) R30.2
N17103301: R32.2 SW1.1(A1) SW1.2(A2) SW1.3(A3)
N17103574: R85.1 U15.5(A0)
N17105483: R67.2 U6.2(PTE1/LLWU_P0)
N17105496: R83.2 TP15.1(TP) U6.58(PTD1)
N17105530: R38.2 U6.63(PTD6/LLWU_P15)
N17105555: R39.2 U6.62(PTD5)
N17105589: R66.2 U6.61(PTD4/LLWU_P14)
N17105614: R40.2 U6.60(PTD3)
N17105656: R41.2 U6.59(PTD2/LLWU_P13)
N17105670: R42.2 U6.54(PTC9)
N17105708: R43.2 U6.53(PTC8)
N17105834: DS4.1(CATHODE) R45.2
N17106014: R48.2 U6.40(PTB17)
N17106031: R49.2 U6.39(PTB16)
N17106052: R50.2 U6.38(PTB3)
N17106071: R51.2 U6.37(PTB2)
N17106085: C46.1 TC1.3(NRESET) U6.34(RESET_B)
N17106116: TC1.4(SWCLK) U6.22(PTA0)
N17106118: TC1.6(SWO) U6.24(PTA2)
N17106120: TC1.2(SWDIO) U6.25(PTA3)
N17109714: J26.2 S1.3 S1.4
N17114657: JP27.2 R98.2 U16.2(S)
N17182443: R108.1 R109.2 U17.3
N17182456: U18.1(S2) U19.3 U20.1 U20.4
N17182464: U18.6(SEL) U19.1
N17182470: U17.1 U17.4 U18.3(S1) U19.4
N17182563: Q5.3(D) R111.1 R113.1 U21.3
N17182569: R112.2 U20.3
N17182581: Q5.1(G) U21.1
N17182601: R110.2 U18.4(D)
N17182603: C74.1 R110.1 U21.4
N17186282: R118.2 U22.4(Y)
N17192183: D1.1(A) R120.1
N17192187: D1.2(K) J31.1
N17192259: C63.2 D1.3(C)
N17192292: J31.2 JP30.1 R122.2
N17192308: C63.1 J29.1
N17192370: C77.1 C83.2 D7.2 J31.3
N17192375: C79.1 C80.2 C81.2 JP31.2 L13.1
N17192465: D7.1 L13.2 Q9.3(DRAIN)
N17192502: J29.3 Q9.1(GATE)
N17301054: R73.2 TP22.1(TP)
N17301055: R77.1 TP19.1(TP)
N17310081: TP16.1(TP) U6.64(PTD7)
N17310082: TP13.1(TP) U6.56(PTC11/LLWU_P11)
N17310083: TP14.1(TP) U6.57(PTC0/LLWU_P12)

Not connected (* = marked no-connect by the designer): FD1 1*; FD2 1*; FD3 1*; FD4 1*; J12 18 19* 20* 28* 29* 30* 31* 43* 44* 45* 46* 47* 48*; J15 4(IO)*; J27 4(IO)*; U3 2(NC)* 3(NC_1)* 9(INT2)* 13(ADC3)* 15(ADC2)* 16(ADC1)*; U6 1(PTE0/CLKOUT32K)* 8(NC)* 9(ADC0_DP0/ADC1_DP3)* 10(ADC0_DM0/ADC1_DM3)* 11(ADC1_DP0/ADC0_DP3)* 12(ADC1_DM0/ADC0_DM3)* 17(VREF_OUT)* 18(DAC0_OUT)* 19(XTAL32)* 20(EXTAL32)* 23(PTA1)* 27(PTA5)* 28(PTA12)* 29(PTA13/LLWU_P4)* 35(PTB0/LLWU_P5)* 36(PTB1)* 41(PTB18)* 42(PTB19)* 43(PTC0)* 50(PTC5/LLWU_P9)* 51(PTC6/LLWU_P10)* 52(PTC7)* 55(PTC10)*; U7 3(2Y1)* 7(3Y1)* 10(N_C_)* 11(4Y1)* 15(1Y1)*; U9 3(2Y1)* 7(3Y1)* 10(N_C_)* 11(4Y1)* 15(1Y1)*; U10 1(1Y0)* 5(2Y0)* 9(3Y0)* 10(N_C_)* 13(4Y0)*; U11 1(1Y0)* 5(2Y0)* 9(3Y0)* 10(N_C_)* 13(4Y0)*; U12 1(1Y0)* 5(2Y0)* 9(3Y0)* 10(N_C_)* 13(4Y0)* 15(1Y1)* 16(1Z)*; U16 1(1Y0)* 5(2Y0)* 9(3Y0)* 10(N_C_)* 13(4Y0)*

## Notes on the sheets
sheet 1
- VDDIO < 1.72V: VCCIO = 1.71V
  VDDIO >=1.72V: VCCIO = VDDIO
- Remove R112 when
  using Interface Board
- Remove R113 when
  using Interface Board
sheet 2
- Common EVB Operation Modes
- ATMOSIC TECHNOLOGIES INC
sheet 3
- ATM3430E EVALUATION BOARD
- Release Date
- Revision
- Design Eng.
- Design Notes
- 07/26/23
- -00
- AD
- Initial release, based on the latest Paris 7x7 EVB, with VDDIO-VCCIO tracking circuit added
- 10/10/23
- -10
- AD
- Added pull-down R123 on BENIGN_BOOT; Ext Flash NL by default; Y1 footprint change; L13 = 47uH
- 9/18/24
- -11
- JoeC
- Add Notes for "Li-Ion Charging Ckts".
- 12/04/24
- -20
- AD
- 1. Added Connector to control Antenna Daughterboard
  2. Changed LED_2 control from P9 to P4 and LED_3 control from P10 to P7 for PWM feature
- 9/29/25
- -23
- AD
- 1. Changed C5 and C6 to 10uF
- ATMOSIC TECHNOLOGIES INC
- Atmosic Technologies, Inc
- 2105 South Bascom Avenue, Suite 220
  Campbell, CA 95008
- Atmosic Technologies Proprietary and Confidential
sheet 4
- Page 1 - Revision notes
  Page 2 - Block diagram
  Page 3 - ATM3430E, decoupling, Li-Ion charging ckt
  Page 4 - GPIO Mapping, Analog switches
  Page 5 - RF matching circuits
  Page 6 - Sensors, Flash, LEDs, Buttons, I/O Interface Connector
  Page 7 - Harvesting and Booster Ckt
  Page 8 - MK22 Controller
  Page 9 - Power supplies and configurations
  Page 10 - VDDIO-VCCIO tracking circuit
  Page 11 - Jumper settings for common Operation Modes
- Block Diagram
- PV Cell
  Conn
- Li-Ion Bat
  Conn
- Ext Supply
  Conn
- USB
  Conn
- On-board Power Supplies
- Harvester
  Booster
- LEDs
- Buttons
- Sensors
- RF Harvester
  Match
- SMA Conn
- Programming
  Pads
- MK22
- 50-pin
  Connector
- Analog
  Switches
- ATM3430E
- Wake-up Rx
  Match
- SMA Conn
- Flash
- GPIOs: P0 - P30
- BLE Tx/Rx
  Match
- SMA Conn
- Reset Button
- ATMOSIC TECHNOLOGIES INC
sheet 5
- Change C12 to 22uF if needs
  to operate below -10°C
- 16MHz XTAL
- Power down switch
- 7X7 QFN
- PTS645 SMD
- Benign boot
- ATMOSIC TECHNOLOGIES INC
- Atmosic Technologies Proprietary and Confidential
sheet 6
- GPIO MUX
- CONNECT SENSORS TO ATM3430
- ISOLATE MK22 FROM ATM3430
- CONNECT FLASH TO ATM3430
- Install to
  connect Sensors
- Install to
  isolate MK22
- Install to
  connect Flash
- CONNECT LEDS/BUTTONS TO ATM3430
- Assert to
  isolate MK22
- Install to
  connect LEDs
  and Buttons
- ATMOSIC TECHNOLOGIES INC
- Atmosic Technologies Proprietary and Confidential
sheet 7
- Reserved for Internal Use Only
- R122 is used for
  measurement only
- J25 - PCB Block Terminal Connector
  Li-Ion Battery wires connect to the PCB here
- PV Cell connector
- J19 - PCB Block Terminal Connector
  PV cell wires connect to the PCB here
- Li-Ion Charging Ckts
- ATMOSIC TECHNOLOGIES INC
sheet 8
- USB ESD
- (Benign Boot
       /
     UART1_RX)
- 90 OHM DIFF PAIR
- USB
- USB OPTION
- MOLEX-105133-031
- J-Link OB
  Programming Pads
- ATMOSIC TECHNOLOGIES INC
sheet 9
- VCC_USB
- Supply for MK22 USB
- VBAT/LI
- VDDIO
- On-Board Voltage Regulators
- For current
  measurements
- Supply for VCCIO
- BAT 2032
- Supply for VBAT
  and/or VCCIO
- For current
  measurements
- Jumper on pins 1-2 for
  external Li-Ion through VBATLI
  Jumper on pins 2-3 to connect
  VBAT to VBATLI for VBAT operation
- VCCIO
- MOUNTING HOLES
- BOARD FIDUCIALS
- ATMOSIC TECHNOLOGIES INC
sheet 10
- BLE front-end match
- Note:
  For inductors, use MHQ series from TDK.
  For capacitors, use Johanson
- RFIO
- ohm
- ESD150-B1-W0201
- WuRx match
- RFIN
- RF Harvester front-end & ANT
- Note: This match is for 915MHz
  Use Murata Wirewound inductors.
  For capacitors, use Johanson.
- RFIN_HARV
- ATMOSIC TECHNOLOGIES INC
- Atmosic Technologies Proprietary and Confidential
sheet 11
- MOTION SENSOR
- LEDS
- BIDS (1Kbits)
- The I2C slave device address: 0x51
- 24AA014
- Antenna Board Control
- SA0: I2C less significant bit of the device address.
  High: 0x19
  Default: input with internal pull-up
- TEMP/HUM SENSOR
- 50-PIN CONNECTOR I/O INTERFACE
- PUSH BUTTONS
- The I2C slave device address of ENS210: 0x43
- PTS645 SMD
- FLASH
- PTS645 SMD
- HARV MODES
- USON 2x3mm
- ATMOSIC TECHNOLOGIES INC
